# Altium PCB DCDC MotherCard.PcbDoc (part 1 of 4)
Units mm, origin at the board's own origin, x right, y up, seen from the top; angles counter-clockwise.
Board outline 252.5 x 130 mm, 6 copper layers (Top Layer, Layer 2, Layer 3, Layer 4, Layer 5, Bottom Layer), stack 1.582 mm thick; 322 components, 189 nets, 1077 pads, 1461 vias.
Unrouted connection lines stored in the file: 2.
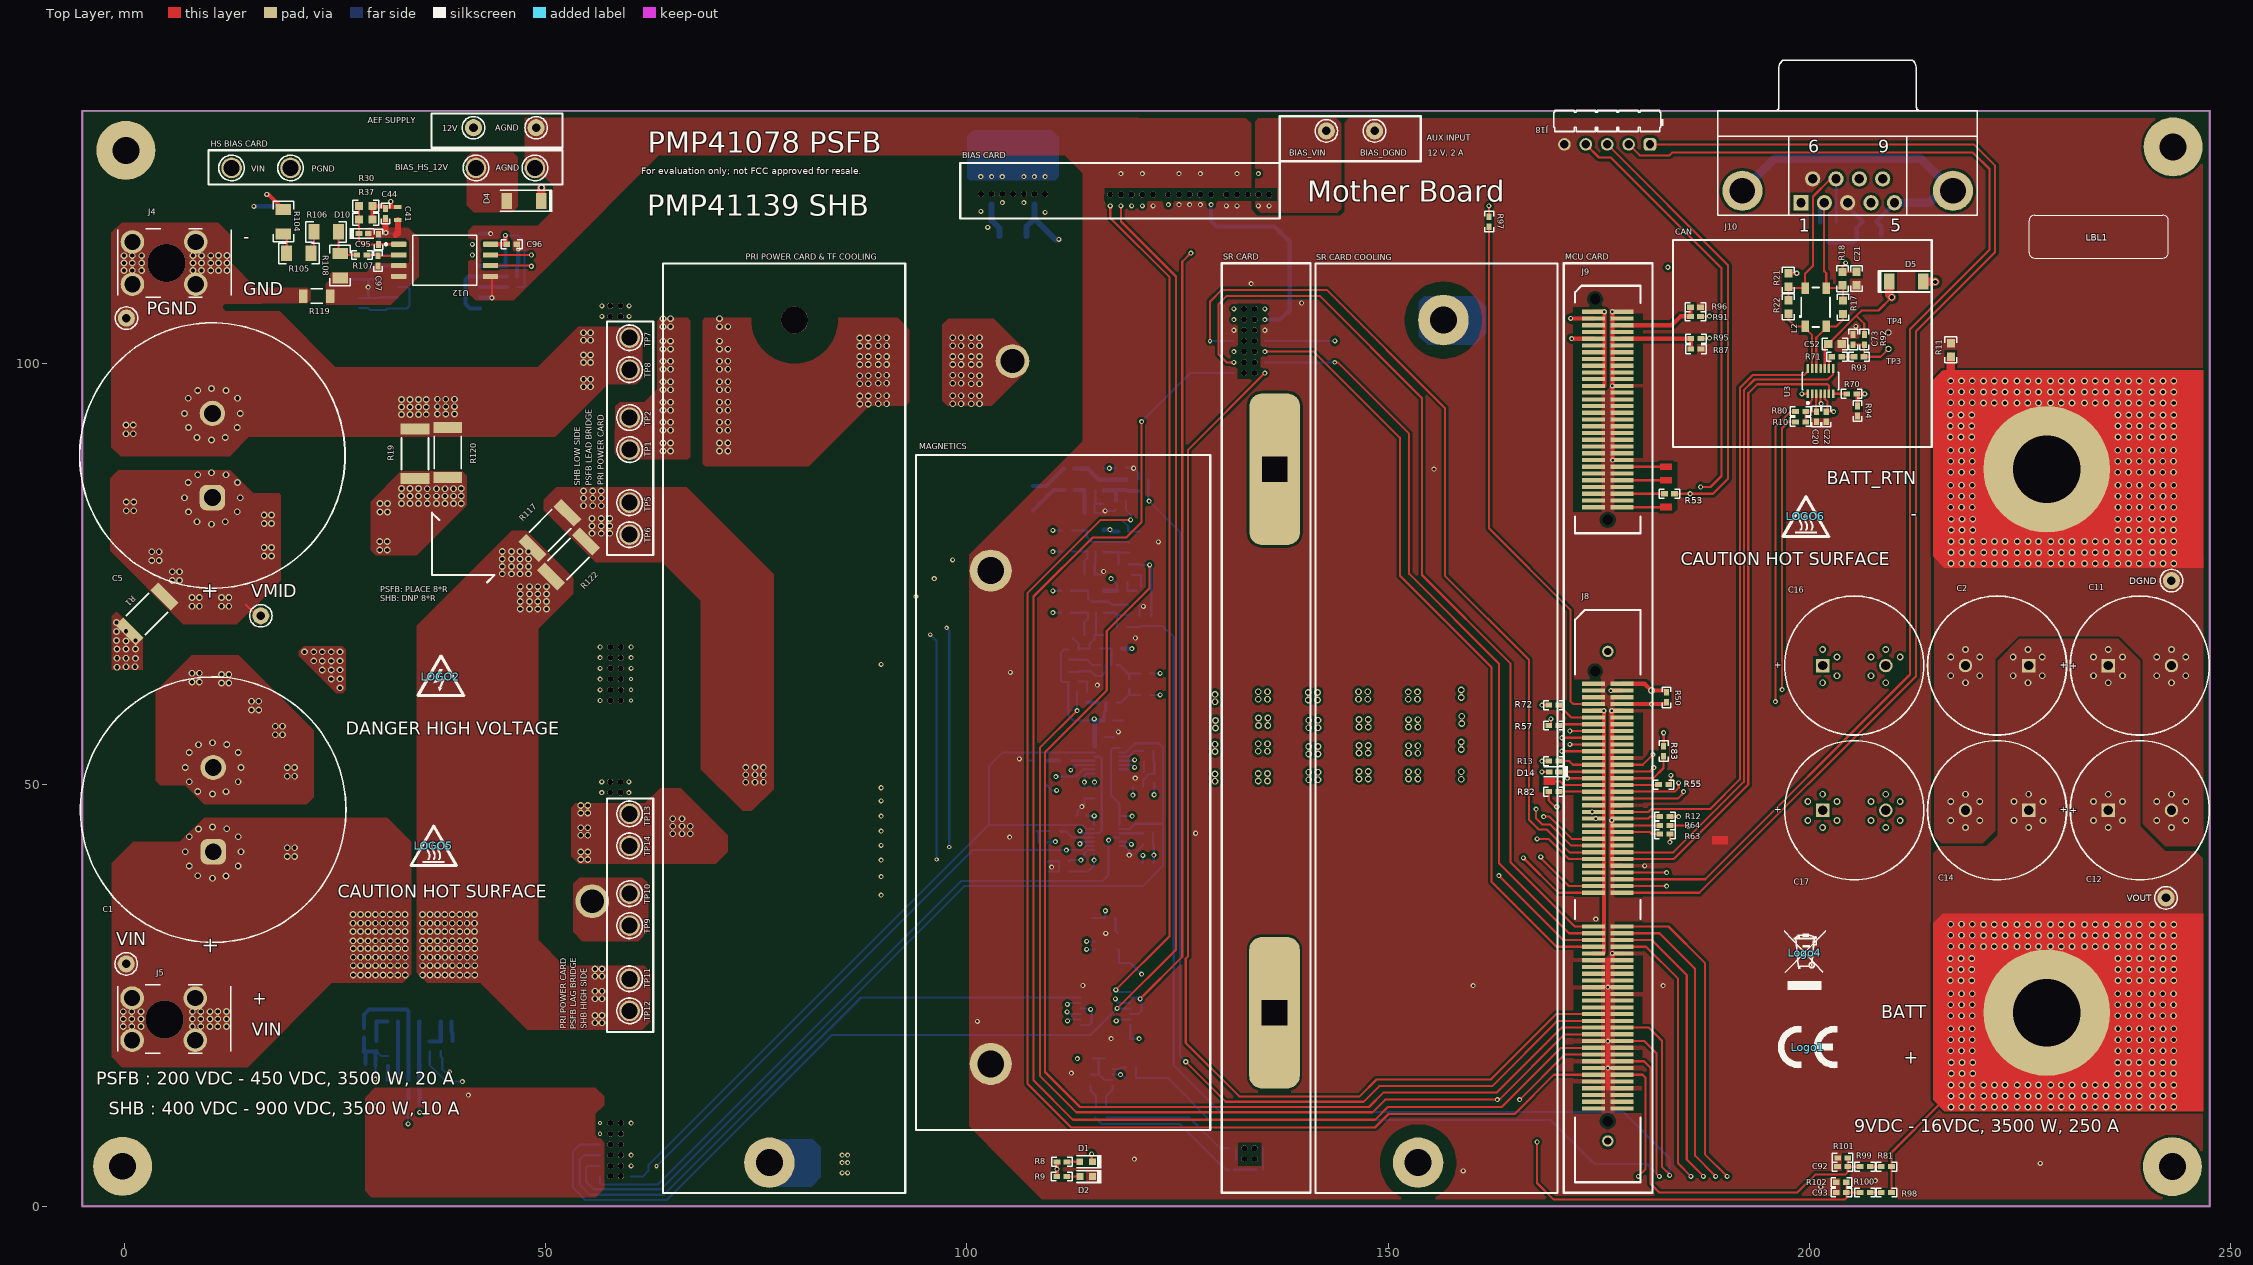
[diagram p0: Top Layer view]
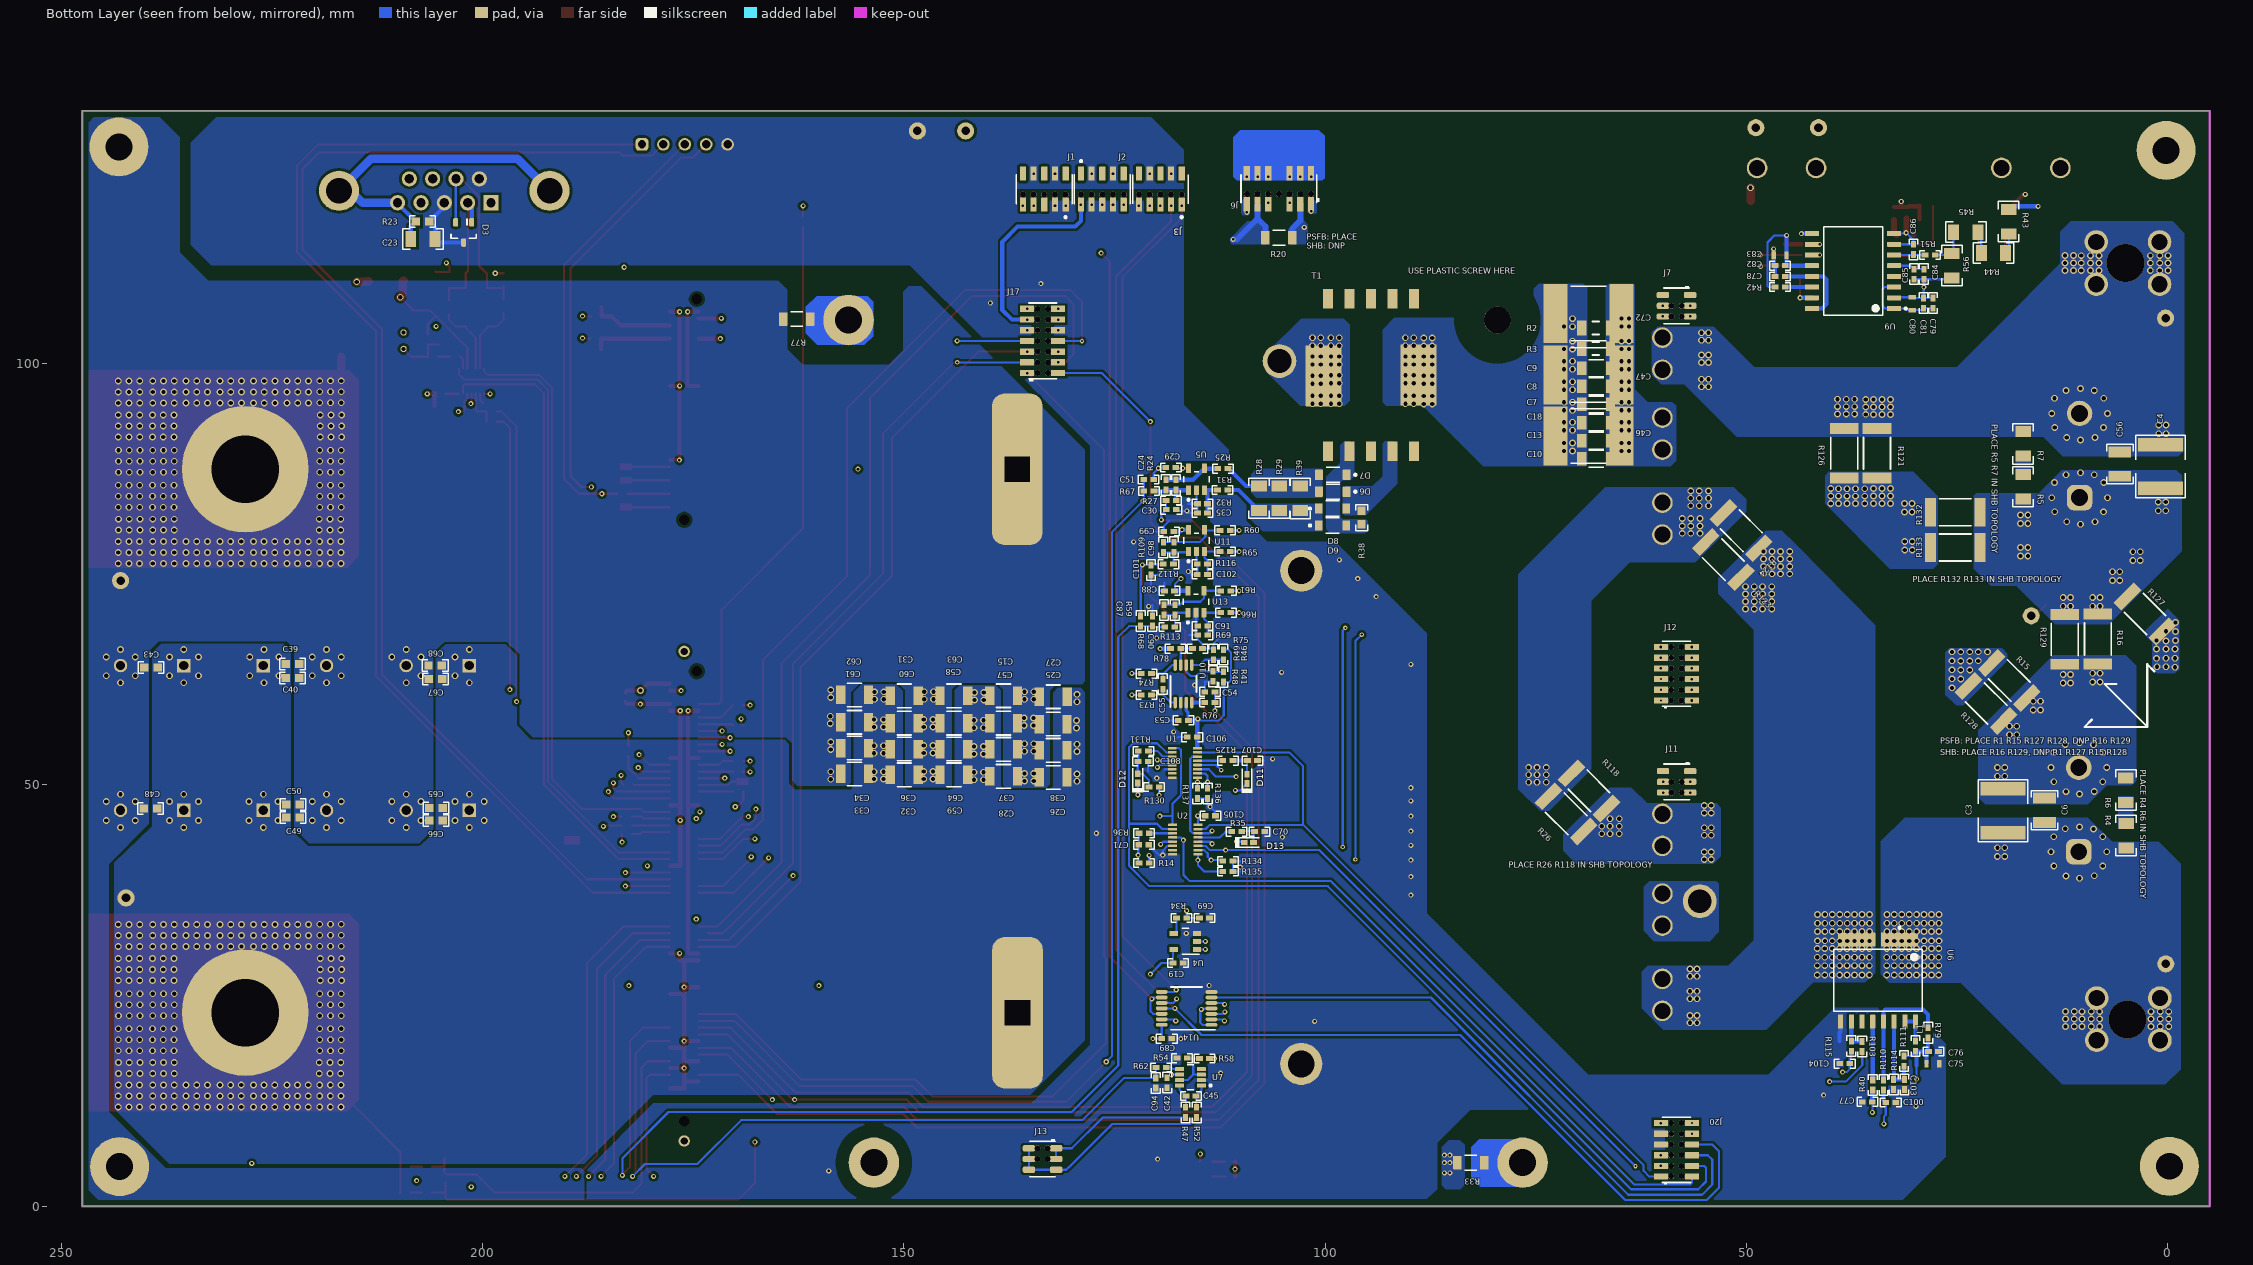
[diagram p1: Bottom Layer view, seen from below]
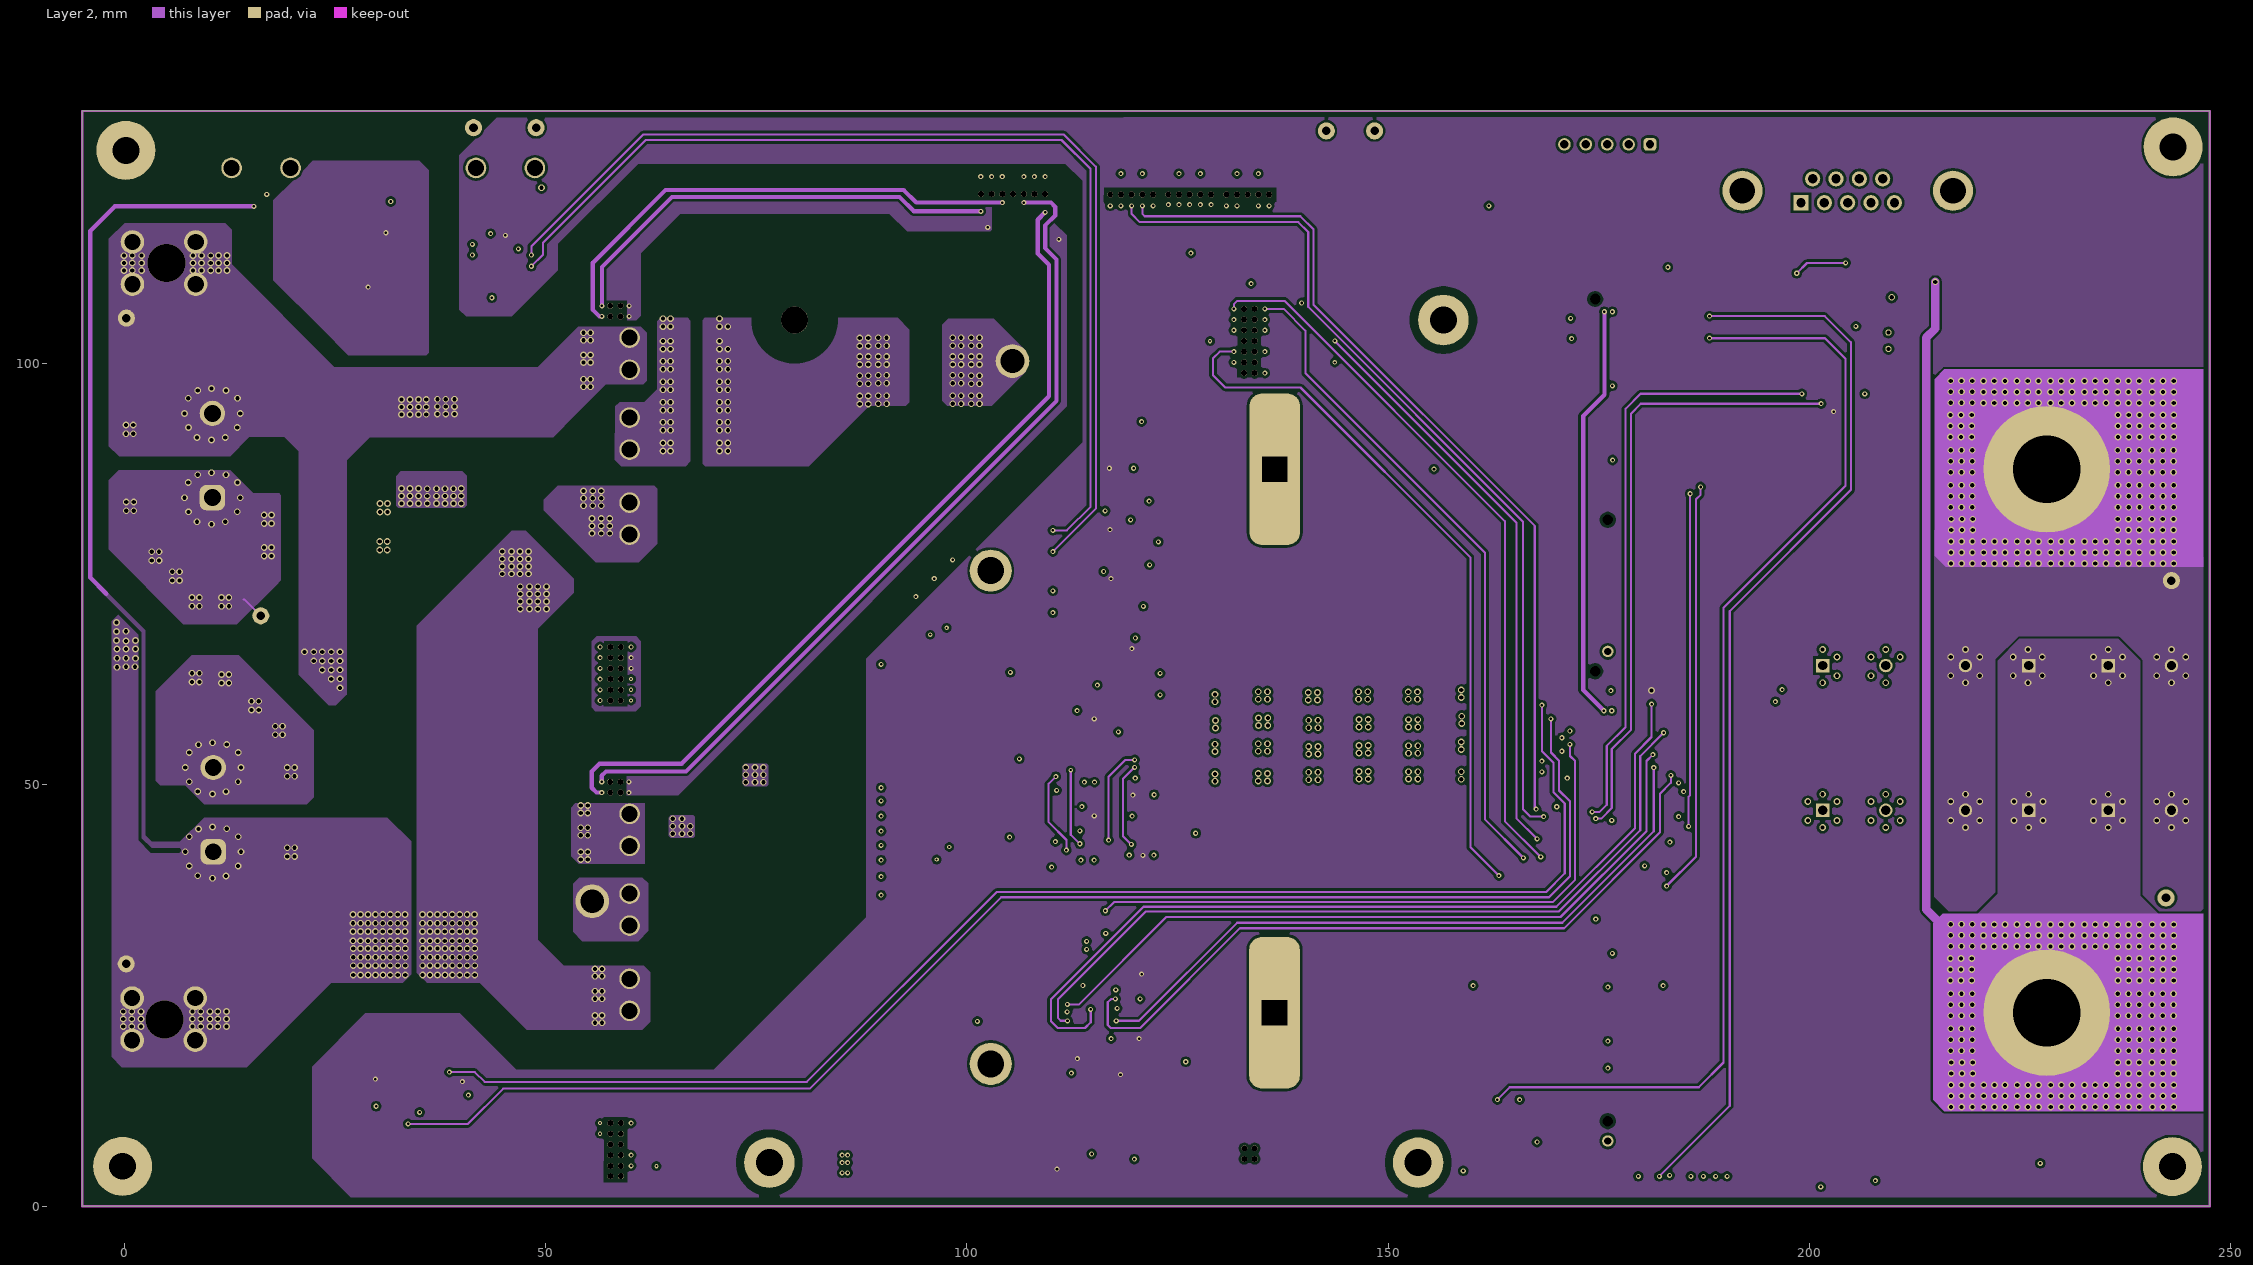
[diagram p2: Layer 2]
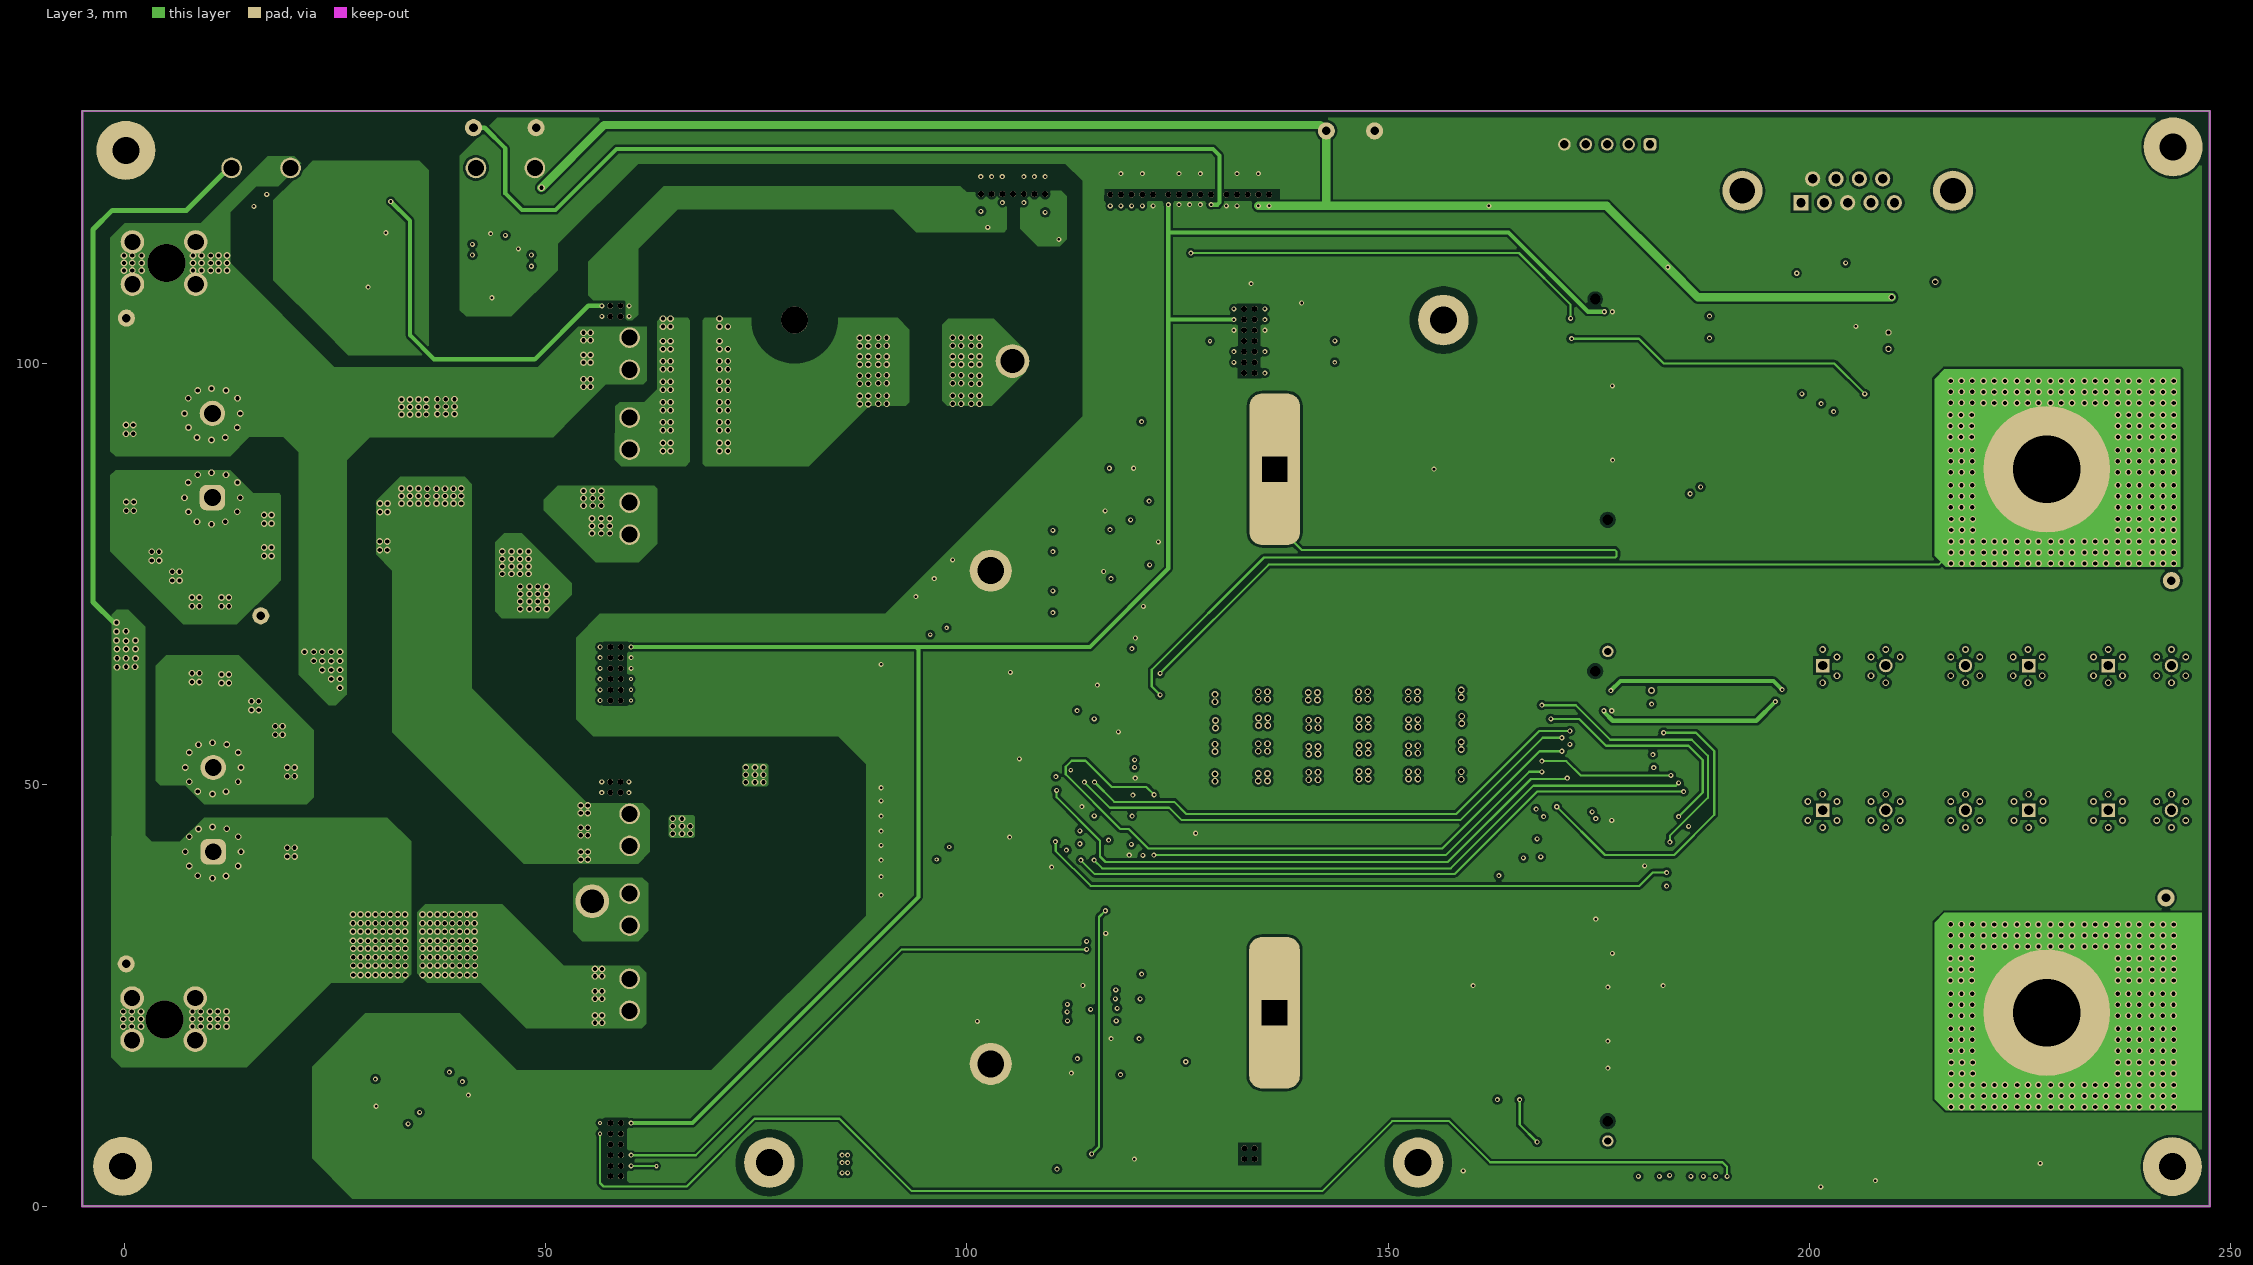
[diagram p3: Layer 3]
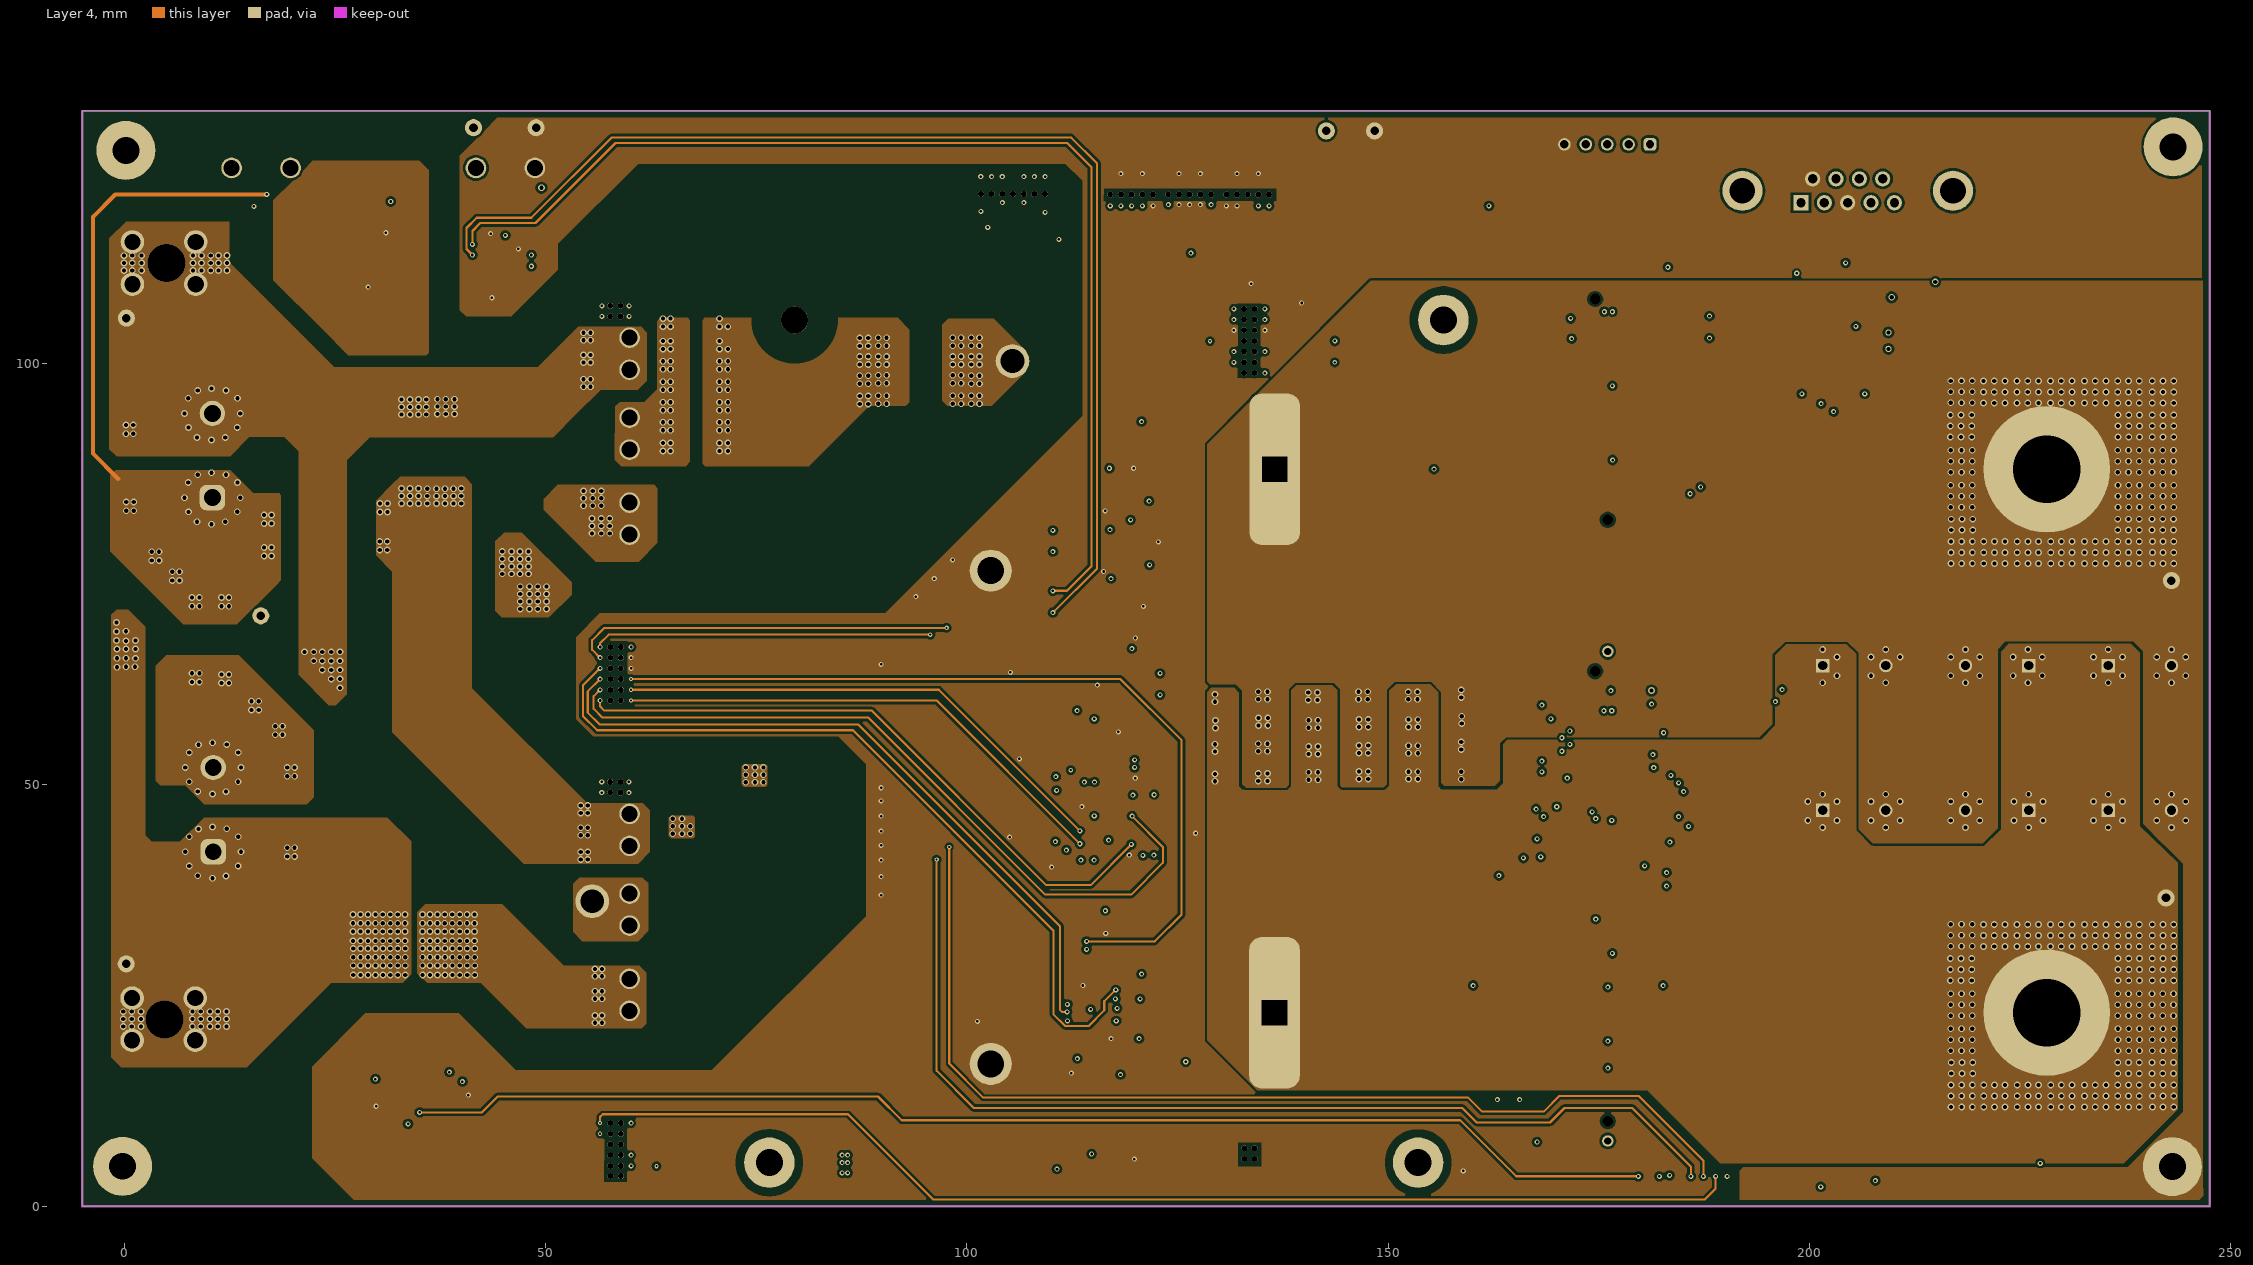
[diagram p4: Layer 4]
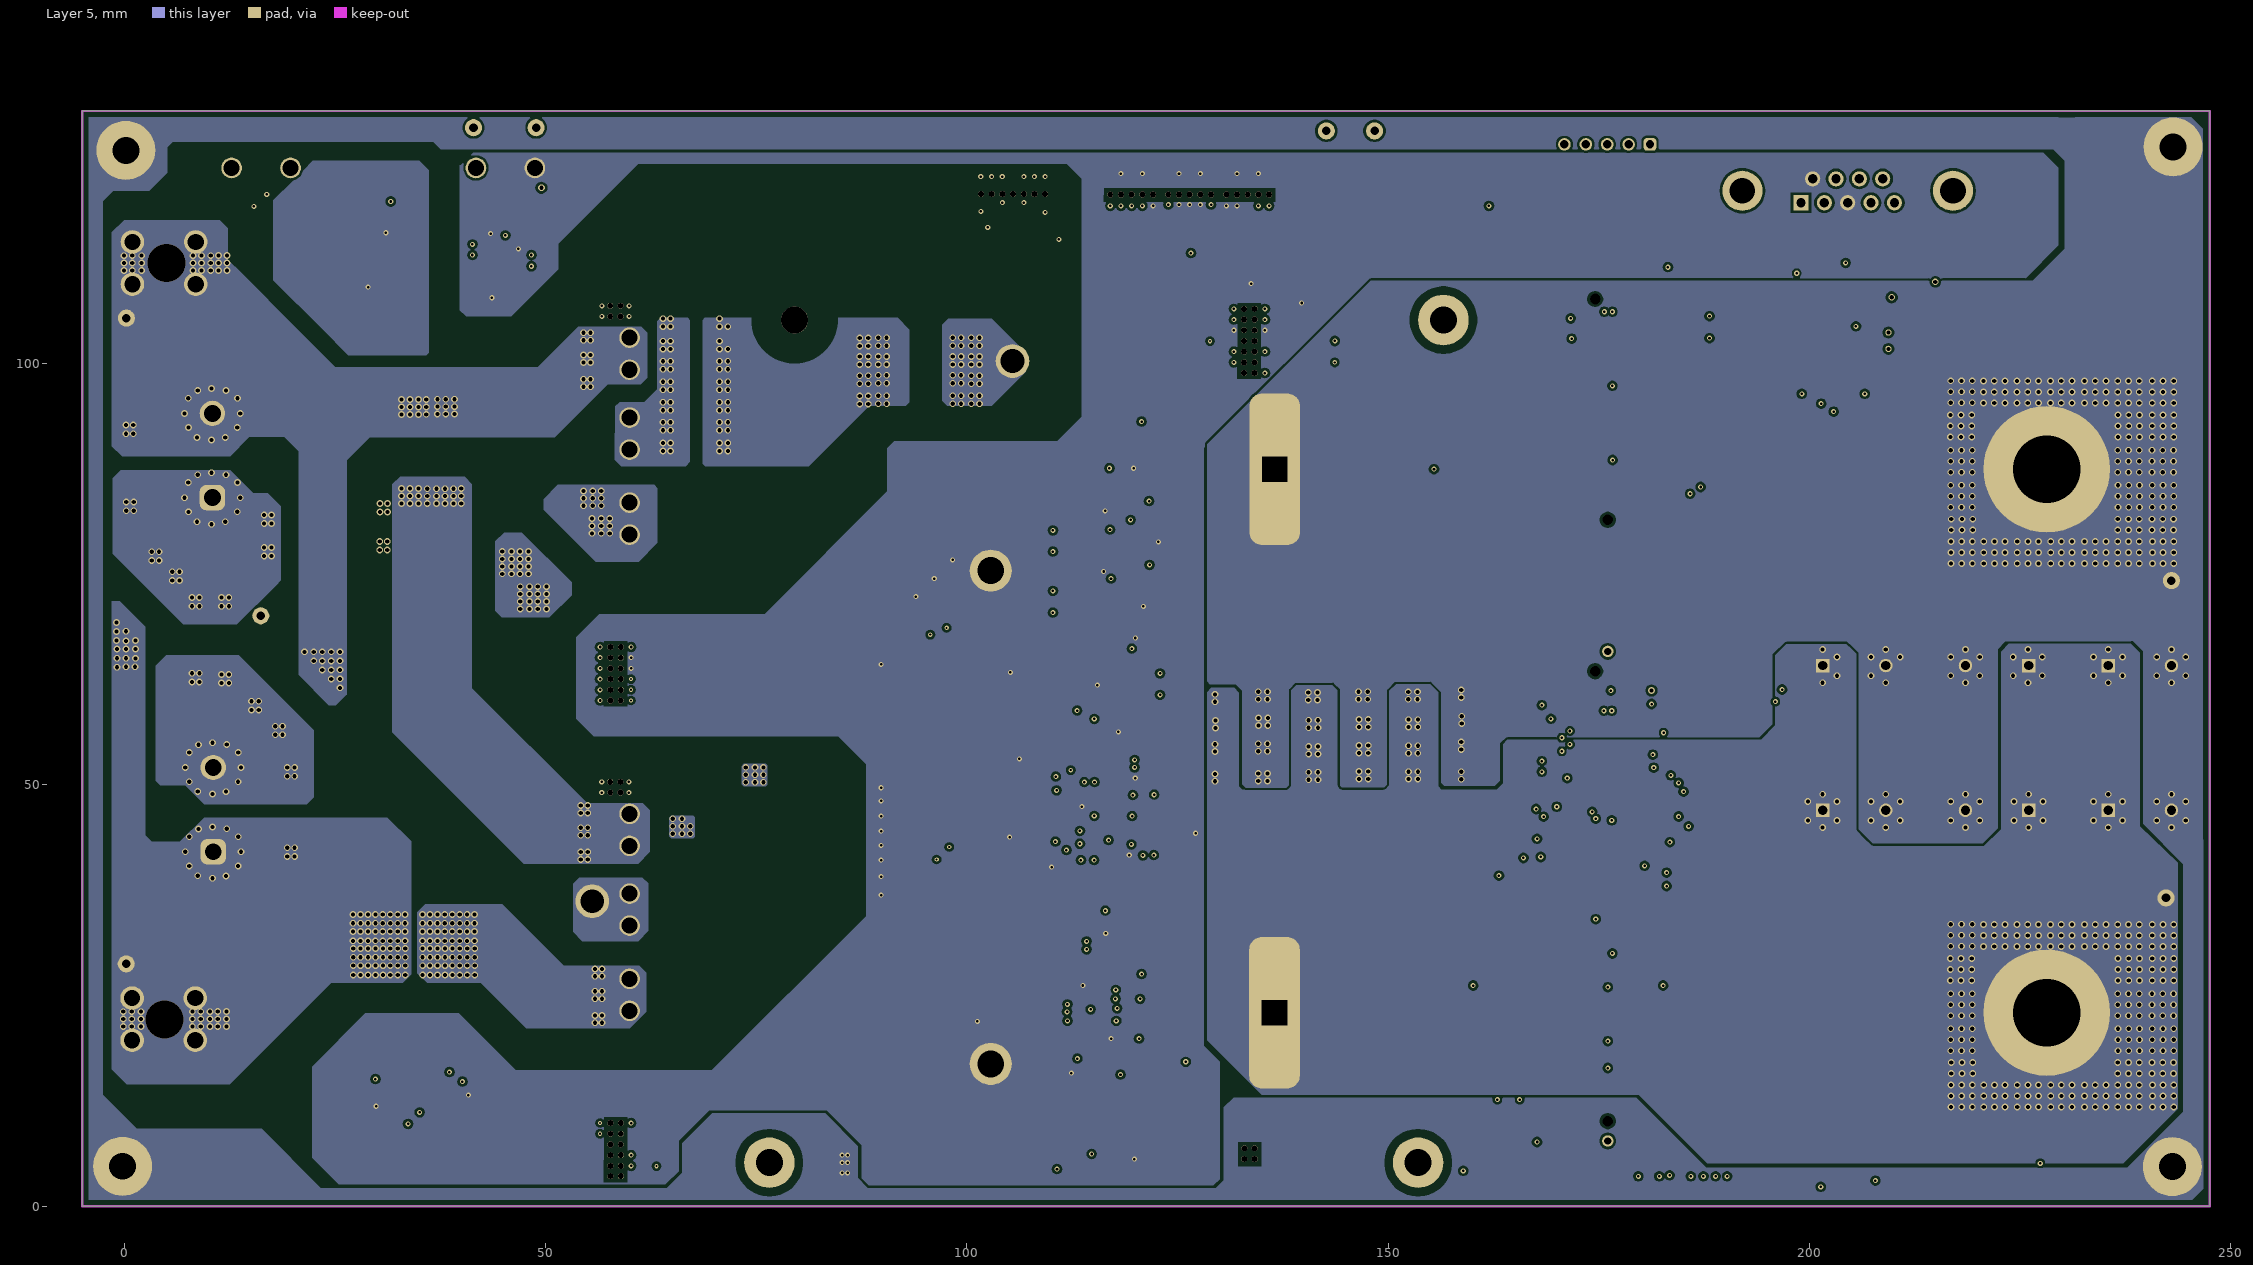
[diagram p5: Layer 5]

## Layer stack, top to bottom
Top Solder: solder mask 0.0102, Solder Resist, Dk 3.5
Top Layer: signal copper 0.07
Dielectric 1: prepreg 0.21, PP-006, Dk 4.1
Layer 2: signal copper 0.07
Dielectric 3: core 0.0711, PP-006, Dk 4.1
Layer 3: signal copper 0.07
Dielectric1: prepreg 0.6, FR-4 High Tg, Dk 4.8
Layer 4: signal copper 0.07
Dielectric 4: core 0.0711, PP-006, Dk 4.1
Layer 5: signal copper 0.07
Dielectric 2: prepreg 0.21, PP-006, Dk 4.1
Bottom Layer: signal copper 0.07
Bottom Solder: solder mask 0.0102, Solder Resist, Dk 3.5

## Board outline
-5,0 -5,130 247.5,130 247.5,0

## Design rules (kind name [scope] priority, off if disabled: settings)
AcuteAngle [All] p1: minimum=4.50000000000000E+0001 checktracksonly=FALSE
AssemblyTestPointUsage [All] p1: valid=2
Clearance Clearance_BoardEdge_MountingHoles [OnCopper and InComponentClass('Mounting Holes') vs IsKeepOut] p1: gap=1.016 ignorepadtopadclearanceinfootprint=FALSE except(0: Arc-Hole Track-Hole SMDPad-Hole THPad-Hole Via-Hole Fill-Hole Poly-Hole Region-Hole Text-Hole)
Clearance Clearance_BoardEdge_Poly [OnCopper and InPoly vs IsKeepOut] p2: gap=0.635 ignorepadtopadclearanceinfootprint=FALSE except(0: Arc-Hole Track-Hole SMDPad-Hole THPad-Hole Via-Hole Fill-Hole Poly-Hole Region-Hole Text-Hole)
Clearance Clearance_BoardEdge [OnCopper and Not InComponentClass('Logo') and not InComponentClass('FiducialMark') and not InRegion(1000,500,4000,800) and Not IsKeepout vs IsKeepOut] p3: gap=0.5 ignorepadtopadclearanceinfootprint=FALSE except(0: Arc-Hole Track-Hole SMDPad-Hole THPad-Hole Via-Hole Fill-Hole Poly-Hole Region-Hole Text-Hole)
Clearance Clearance_Poly [InPolygon] p4: gap=0.3 ignorepadtopadclearanceinfootprint=FALSE except(0: Arc-Hole Track-Hole SMDPad-Hole THPad-Hole Via-Hole Fill-Hole Poly-Hole Region-Hole Text-Hole)
Clearance [All] p5: gap=0.2 ignorepadtopadclearanceinfootprint=FALSE except(0: Arc-Hole Track-Hole SMDPad-THPad SMDPad-Hole THPad-Hole Via-Hole Fill-Hole Poly-Hole Region-Hole Text-Hole)
ComponentClearance ComponentClearance_Logo [All] p1 off: gap=0.254 collisioncheckmode=3 verticalgap=0.254 showdistances=TRUE
ComponentClearance ComponentClearance_ScrewToNut [(HasFootprint('NY PMS 440 0025 PH')) vs (HasFootprint('Keystone_1902C'))] p2 off: gap=0.127 collisioncheckmode=3 verticalgap=0.254 showdistances=FALSE
ComponentClearance ComponentClearance_MountingHoles [InComponentClass('Mounting Holes')] p3 off: gap=0.254 collisioncheckmode=3 verticalgap=2540 showdistances=FALSE
ComponentClearance ComponentClearance_SmallPassives [HasFootprint('0201*') or HasFootprint('0402*') or HasFootprint('0508') or HasFootprint('0603*') or HasFootprint('0612') or HasFootprint('0805*') or HasFootprint('0815*') or HasFootprint('0830*') or HasFootprint('1206*') or HasFootprint('1210*') or HasFootprint('1808*') or HasFootprint('1812*') or HasFootprint('1825*') or HasFootprint('2010*') or HasFootprint('2220*') or HasFootprint('2225*') or HasFootprint('2512*') or HasFootprint('2728*') or HasFootprint('3518*') vs HasFootprint('0201*') or HasFootprint('0402*') or HasFootprint('0508') or HasFootprint('0603*') or HasFootprint('0612') or HasFootprint('0805*') or HasFootprint('0815*') or HasFootprint('0830*') or HasFootprint('1206*') or HasFootprint('1210*') or HasFootprint('1808*') or HasFootprint('1812*') or HasFootprint('1825*') or HasFootprint('2010*') or HasFootprint('2220*') or HasFootprint('2225*') or HasFootprint('2512*') or HasFootprint('2728*') or HasFootprint('3518*')] p4 off: gap=0.254 collisioncheckmode=3 verticalgap=0.254 showdistances=FALSE
ComponentClearance ComponentClearance_THtoSMT [IsThruComponent vs IsSMTComponent] p5 off: gap=0.254 collisioncheckmode=3 verticalgap=2540 showdistances=FALSE
ComponentClearance ComponentClearance_THtoTH [IsThruComponent vs IsThruComponent] p6 off: gap=0.254 collisioncheckmode=3 verticalgap=2540 showdistances=FALSE
ComponentClearance [All] p7 off: gap=0.254 collisioncheckmode=3 verticalgap=0.254 showdistances=FALSE
DiffPairsRouting [All] p1: maxlimit=2.54 minlimit=0.254 mostfreqgap=0.254 toplayer_minwidth=0.381 toplayer_maxwidth=0.381 toplayer_prefwidth=0.381 midlayer1_minwidth=0.381 midlayer1_maxwidth=0.381 midlayer1_prefwidth=0.381 midlayer2_minwidth=0.381 midlayer2_maxwidth=0.381 midlayer2_prefwidth=0.381 midlayer3_minwidth=0.381 midlayer3_maxwidth=0.381 midlayer3_prefwidth=0.381 midlayer4_minwidth=0.381 midlayer4_maxwidth=0.381 midlayer4_prefwidth=0.381 bottomlayer_minwidth=0.381 bottomlayer_maxwidth=0.381 bottomlayer_prefwidth=0.381 maxuncoupledlength=25.4
FabricationTestPointUsage TestPointUsage [All] p1: valid=2 allowmultiple=FALSE
FabricationTestpoint Testpoint [All] p1: side=3 testpointundercomponent=TRUE minsize=1.016 maxsize=2.54 preferedsize=1.524 minholesize=0 maxholesize=1.016 preferedholesize=0.813 testpointgrid=0.025 allowsidetop=TRUE allowsidebottom=TRUE usegrid=TRUE gridtolerance=0
FanoutControl Fanout_LCC [IsLCC] p1: bgadir=Out bgaviamode=Centered fanoutstyle=Auto fanoutdirection=Alternating viagrid=0.025 // Fanout_LCC (Default Rule)
FanoutControl Fanout_BGA [IsBGA] p2: bgadir=Out bgaviamode=Centered fanoutstyle=Auto fanoutdirection=Alternating viagrid=0.025 // Fanout_BGA (Default Rule)
FanoutControl Fanout_Default [All] p4: bgadir=Out bgaviamode=Centered fanoutstyle=Auto fanoutdirection=Alternating viagrid=0.025 // Fanout_Default (Default Rule)
FanoutControl Fanout_Small [(CompPinCount < 5)] p5: bgadir=Out bgaviamode=Centered fanoutstyle=Auto fanoutdirection=OutThenIn viagrid=0.025 // Fanout_Small (Default Rule)
Height [All] p1: minheight=0 maxheight=80 prefheight=12.7
HoleSize [All] p1: absolutevalues=TRUE maxlimit=20 minlimit=0.152 maxpercent=80.000 minpercent=20.000
MinimumAnnularRing [All] p1: minimumring=0
MinimumSolderMaskSliver MinimumSolderMaskSliver_Logo [InComponentClass('Logo') vs InComponentClass('Logo')] p1: minsoldermaskwidth=0.018
MinimumSolderMaskSliver [All] p2: minsoldermaskwidth=0
NetsToIgnore [InNet('No Net')] p1:
PlaneConnect [All] p1: planeconnectstyle=Direct reliefexpansion=0.254 reliefentries=4 reliefconductorwidth=0.254 reliefairgap=0.254
PolygonConnect [All] p1: connectstyle=Direct reliefconductorwidth=0.254 reliefentries=4 polygonreliefangle="90 Angle" airgapwidth=0.254
RoutingCorners [All] p1: cornerstyle=45-Degree minsetback=0.254 maxsetback=2.54
RoutingVias [All] p1: holewidth=0.406 width=0.864 viastyle="Through Hole" minholewidth=0.203 minwidth=0.406 maxholewidth=6 maxwidth=6
SMDToCorner [All] p1: distance=0
SilkToBoardRegionClearance [Not ((IsComment or IsDesignator) And (Hide <> 'False')) and not InRegion(1000,500,4000,800)] p1:
SilkToSilkClearance [All] p1: silktosilkclearance=0
SilkToSolderMaskClearance SilkscreenOverComponentPads [IsPad] p1: minsilkscreentomaskgap=0 clearancetoexposedcopper=TRUE
SolderMaskExpansion [All] p1: expansion=0.076 istentingtop=FALSE
Width [All] p1: maxlimit=2.54 minlimit=0.152 preferedwidth=0.254 checkconnectedcopper=TRUE
13 further rules are at their usual default settings.

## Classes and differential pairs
component class Header: J18
net class VSW: LAG_SW LEAD_SW LEAD_SW_R
net class VHV: 3V3 AGND I_HV_2 I_HV_FILTER LEAD_SW_R NetC24_1 NetC24_2 NetC35_1 NetD6_1 NetD6_2 NetD7_1 NetD8_1 NetT1_1 NetT1_3 NetT1_5 NetT1_6 NetT1_7 NetT1_8 NetT1_9 NetT1_10 VIN VPRI+
net class PGND: AGNDM AGNDP LAG_ISO_12V_L LAG_ISO_-5V_L LEAD_ISO_12V_L LEAD_ISO_-5V_L "NC U4" NetC1_2 NetC79_1 NetC84_1 NetC86_1 NetJ6_5 NetR43_2 NetR44_2 NetR45_2
component class "V Sensor": C41 C44 C78 C79 C80 C81 C82 C83 C84 C85 C86 C87 C88 C90 C91 C92 C93 C95 C96 C97 C98 C99 C101 C102 D10 R30 R37 R42 R43 R44 R45 R51 R56 R59 R60 R61 R65 R66 R68 R69 R81 R98 R99 R100 R101 R102 R104 R105 R106 R107 R108 R109 R112 R113 R116 R119 U9 U11 U12 U13
component class PowerStage: 12V AGND BIAS_DGND BIAS_HS_12V BIAS_VIN C1 C2 C3 C4 C5 C6 C7 C8 C9 C10 C11 C12 C13 C14 C15 C16 C17 C18 C25 C26 C27 C28 C31 C32 C33 C34 C36 C37 C38 C39 C40 C43 C46 C47 C48 C49 C50 C56 C57 C58 C59 C60 C61 C62 C63 C64 C65 C66 C67 C68 C72 D4 D5 DGND J1 J2 J3 J4 J5 J6 J7 J11 J12 J13 J17 J20 PGND R1 R2 R3 R4 R5 R6 R7 R15 R16 R19 R20 R26 R33 R77 R117 R118 R120 R121 R122 R123 R124 R126 R127 R128 R129 R132 R133 TP1 TP2 TP5 TP6 TP7 TP8 TP9 TP10 TP11 TP12 TP13 TP14 VIN VMID VOUT
component class "I Sensor": C24 C29 C30 C35 C42 C45 C51 C53 C54 C55 C75 C76 C77 C94 C100 C103 C104 D6 D7 D8 D9 L1 R24 R25 R27 R28 R29 R31 R32 R38 R39 R40 R41 R46 R47 R48 R49 R52 R54 R58 R62 R67 R73 R74 R75 R76 R78 R79 R103 R110 R111 R114 R115 T1 U5 U6 U7 U10
component class Controller: C19 C20 C21 C22 C23 C52 C69 C70 C71 C73 C89 C105 C106 C107 C108 D1 D2 D3 D11 D12 D13 D14 J8 J9 J10 J18 L2 R8 R9 R10 R11 R12 R13 R14 R17 R18 R21 R22 R23 R34 R35 R36 R50 R53 R55 R57 R63 R64 R70 R71 R72 R80 R82 R83 R87 R91 R92 R93 R94 R95 R96 R97 R125 R130 R131 R134 R135 R136 R137 TP3 TP4 U1 U2 U3 U4 U14
component class "DCDC MotherCard_Hardware": LBL1 Logo1 LOGO2 Logo3 Logo4 LOGO5 LOGO6 ZZ1 ZZ2 ZZ3 ZZ4
component class AssemblyNote: ZZ1 ZZ2 ZZ3 ZZ4
component class Label: LBL1

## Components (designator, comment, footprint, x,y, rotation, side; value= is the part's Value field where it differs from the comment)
12V "5000" Keystone5000 41.438,128 r0 top
AGND "0312-0-15-15-34-27-10-0" Mill-Max_0312-0-15-15-34-27-10-0 48.728,123.225 r90 top
AGND "5001" Keystone5001 48.871,128 r90 top
BIAS_DGND "5001" Keystone5001 148.375,127.625 r90 top
BIAS_HS_12V "0312-0-15-15-34-27-10-0" Mill-Max_0312-0-15-15-34-27-10-0 41.729,123.225 r90 top
BIAS_VIN "5000" Keystone5000 142.65,127.625 r90 top
C1 "LGN2X121MELB45" Nichicon_3000x4500_Snap 10.55,47.075 r90 top value=120uF
C2 "B41896C7188M000" B41896_1600x3150 222.25,64.173 r180 top value=1800uF
C3 "CGA9P1X7T2J474M250KC" 2220_280 19.541,46.95 r90 bottom value=0.47uF
C4 "CGA9P1X7T2J474M250KC" 2220_280 0.857,87.791 r90 bottom value=0.47uF
C5 "LGN2X121MELB45" Nichicon_3000x4500_Snap 10.45,89.1 r90 top value=120uF
C6 "CGA6J4C0G2J103J125AA" 1210_150 14.625,47.009 r90 bottom value=0.01uF
C7 "CGA5L3X7R1H225K160AB" 1206_180 67.825,95.157 r180 bottom value=2.2uF
C8 "CGA5L3X7R1H225K160AB" 1206_180 67.825,97.303 r180 bottom value=2.2uF
C9 "CGA5L3X7R1H225K160AB" 1206_180 67.825,99.45 r180 bottom value=2.2uF
C10 "CGA5L3X7R1H225K160AB" 1206_180 67.825,88.717 r180 bottom value=2.2uF
C11 "B41896C7188M000" B41896_1600x3150 239.2,64.173 r0 top value=1800uF
C12 "B41896C7188M000" B41896_1600x3150 239.2,47 r0 top value=1800uF
C13 "CGA5L3X7R1H225K160AB" 1206_180 67.825,90.863 r180 bottom value=2.2uF
C14 "B41896C7188M000" B41896_1600x3150 222.25,47 r180 top value=1800uF
C15 "CGA6P3X7S1H106K250AE" 1210_280 138.15,60.594 r180 bottom value=10uF
C16 "B41896C7188M000" B41896_1600x3150 205.3,64.173 r0 top value=1800uF
C17 "B41896C7188M000" B41896_1600x3150 205.3,47 r0 top value=1800uF
C18 "CGA5L3X7R1H225K160AB" 1206_180 67.825,93.01 r180 bottom value=2.2uF
C19 "CGA2B3X7R1E104K050BB" 0402 117.441,28.865 r180 bottom value=0.1uF
C20 "CGA2B3X7R1E104K050BB" 0402 200.801,93.703 r270 top value=0.1uF
C21 "CGA3E2X7R2A472K080AA" 0603 205.55,110.125 r270 top value=4700pF
C22 "CGA2B3X7R1E104K050BB" 0402 201.981,93.703 r270 top value=0.1uF
C23 "C1206C103J2GACAUTO" 1206 207.059,114.8 r180 bottom value=0.01uF
C24 "04025U100CAT2A" 0402 118.903,85.617 r90 bottom value=10pF
C25 "CGA6P3X7S1H106K250AE" 1210_280 132.262,57.231 r0 bottom value=10uF
C26 "CGA6P3X7S1H106K250AE" 1210_280 132.262,50.896 r0 bottom value=10uF
C27 "CGA6P3X7S1H106K250AE" 1210_280 132.255,60.471 r0 bottom value=10uF
C28 "CGA6P3X7S1H106K250AE" 1210_280 138.155,51.019 r180 bottom value=10uF
C29 "CGA2B3X7R1E104K050BB" 0402 118.308,87.685 r0 bottom value=0.1uF
C30 "AC0402KRX7R7BB221" 0402 118.254,82.668 r180 bottom value=220pF
C31 "CGA6P3X7S1H106K250AE" 1210_280 149.939,60.58 r180 bottom value=10uF
C32 "CGA6P3X7S1H106K250AE" 1210_280 149.941,51.205 r180 bottom value=10uF
C33 "CGA6P3X7S1H106K250AE" 1210_280 155.834,51.306 r0 bottom value=10uF
C34 "CGA6P3X7S1H106K250AE" 1210_280 155.834,54.381 r0 bottom value=10uF
C35 "04025U100CAT2A" 0402 114.54,82.278 r0 bottom value=10pF
C36 "CGA6P3X7S1H106K250AE" 1210_280 149.941,54.266 r180 bottom value=10uF
C37 "CGA6P3X7S1H106K250AE" 1210_280 138.155,54.229 r180 bottom value=10uF
C38 "CGA6P3X7S1H106K250AE" 1210_280 132.262,54.106 r0 bottom value=10uF
C39 "06035C104KAZ2A" 0603 222.525,64.371 r180 bottom value=0.1uF
C40 "06035C104KAZ2A" 0603 222.525,62.712 r180 bottom value=0.1uF
C41 "CGA3E1X7R1E105K080AC" 0603S 32.462,117.822 r270 top value=1uF
C42 "CGA2B3X7R1E104K050BB" 0402 118.743,14.667 r270 bottom value=0.1uF
C43 "06035C104KAZ2A" 0603 239.35,63.95 r0 bottom value=0.1uF
C44 "CGA2B3X7R1E104K050BB" 0402 30.993,117.822 r270 top value=0.1uF
C45 "AC0402KRX7R7BB221" 0402 115.917,13.091 r180 bottom value=220pF
C46 "B58035U7105M052" FP-B58035U7105M052_SMD2-MFG 68.725,91.412 r0 bottom value=1µF
C47 "B58035U7105M052" FP-B58035U7105M052_SMD2-MFG 68.725,98.658 r0 bottom value=1µF
C48 "06035C104KAZ2A" 0603 239.375,47.2 r0 bottom value=0.1uF
C49 "06035C104KAZ2A" 0603 222.475,46.125 r180 bottom value=0.1uF
C50 "06035C104KAZ2A" 0603 222.475,47.675 r180 bottom value=0.1uF
C51 "GCM155R71H222KA37D" 0402 120.931,86.252 r180 bottom value=2200pF
C52 "06035C104KAZ2A" 0603 203,102.333 r0 top value=0.1uF
C53 "CGA2B3X7R1E104K050BB" 0402 116.809,57.672 r0 bottom value=0.1uF
C54 "AC0402KRX7R7BB221" 0402 113.666,61.055 r0 bottom value=220pF
C55 "AC0402KRX7R7BB221" 0402 119.258,61.958 r90 bottom value=220pF
C56 "CGA6J4C0G2J103J125AA" 1210_150 5.681,88.091 r90 bottom value=0.01uF
C57 "CGA6P3X7S1H106K250AE" 1210_280 138.155,57.341 r180 bottom value=10uF
C58 "CGA6P3X7S1H106K250AE" 1210_280 144.048,57.339 r0 bottom value=10uF
C59 "CGA6P3X7S1H106K250AE" 1210_280 144.048,54.266 r0 bottom value=10uF
C60 "CGA6P3X7S1H106K250AE" 1210_280 149.941,57.339 r180 bottom value=10uF
C61 "CGA6P3X7S1H106K250AE" 1210_280 155.834,57.441 r0 bottom value=10uF
C62 "CGA6P3X7S1H106K250AE" 1210_280 155.834,60.681 r0 bottom value=10uF
C63 "CGA6P3X7S1H106K250AE" 1210_280 144.045,60.58 r0 bottom value=10uF
C64 "CGA6P3X7S1H106K250AE" 1210_280 144.048,51.205 r0 bottom value=10uF
C65 "06035C104KAZ2A" 0603 205.525,47.267 r0 bottom value=0.1uF
C66 "06035C104KAZ2A" 0603 205.525,45.782 r0 bottom value=0.1uF
C67 "06035C104KAZ2A" 0603 205.561,62.575 r0 bottom value=0.1uF
C68 "06035C104KAZ2A" 0603 205.605,64.173 r0 bottom value=0.1uF
C69 "GCM155R71H222KA37D" 0402 114.312,34.224 r180 bottom value=2200pF
C70 "GCM155R71H222KA37D" 0402 107.768,44.458 r180 bottom value=2200pF
C71 "GCM155R71H222KA37D" 0402 121.509,42.908 r180 bottom value=2200pF
C72 "B58035U7105M052" FP-B58035U7105M052_SMD2-MFG 68.725,105.941 r0 bottom value=1µF
C73 "CGA2B3X7R1H103K050BB" 0402 205.179,102.853 r90 top value=0.01uF
C75 "CGA3E1X7R1E105K080AC" 0603S 27.869,16.925 r180 bottom value=1uF
C76 "CGA2B3X7R1E104K050BB" 0402 27.795,18.365 r180 bottom value=0.1uF
C77 "AC0402KRX7R7BB221" 0402 35.65,12.39 r0 bottom value=220pF
C78 "CGA2B3X7R1E104K050BB" 0402 45.993,110.356 r0 bottom value=0.1uF
C79 "CGA2B3X7R1E104K050BB" 0402 27.843,107.191 r90 bottom value=0.1uF
C80 "CGA3E1X7R1E105K080AC" 0603S 30.293,107.116 r90 bottom value=1uF
C81 "GCM155R71H222KA37D" 0402 28.968,107.191 r90 bottom value=2200pF
C82 "GCM155R71H222KA37D" 0402 46,111.626 r0 bottom value=2200pF
C83 "CGA3E1X7R1E105K080AC" 0603S 46,112.896 r0 bottom value=1uF
C84 "CGA2B3X7R1E104K050BB" 0402 28.943,110.616 r270 bottom value=0.1uF
C85 "GCM155R71H222KA37D" 0402 30.118,110.616 r270 bottom value=2200pF
C86 "CGA2B3X7R1H103K050BB" 0402 30.168,113.566 r90 bottom value=0.01uF
C87 "AC0402KRX7R7BB221" 0402 119.108,70.786 r270 bottom value=220pF
C88 "CGA2B3X7R1E104K050BB" 0402 118.464,73.043 r0 bottom value=0.1uF
C89 "CGA2B3X7R1E104K050BB" 0402 118.789,19.889 r180 bottom value=0.1uF
C90 "AC0402KRX7R7BB221" 0402 120.499,69.455 r90 bottom value=220pF
C91 "AC0402KRX7R7BB221" 0402 114.521,68.855 r0 bottom value=220pF
C92 "AC0402KRX7R7BB221" 0402 203.926,4.7 r180 top value=220pF
C93 "AC0402KRX7R7BB221" 0402 203.765,1.629 r180 top value=220pF
C94 "AC0402KRX7R7BB221" 0402 120.091,14.638 r270 bottom value=220pF
C95 "CGA2B3X7R1E104K050BB" 0402 30.168,114.751 r90 top value=0.1uF
C96 "CGA2B3X7R1E104K050BB" 0402 45.981,114.171 r0 top value=0.1uF
C97 "CGA2B3X7R1H103K050BB" 0402 30.118,112.195 r270 top value=0.01uF
C98 "AC0402KRX7R7BB221" 0402 117.938,78.217 r270 bottom value=220pF
C99 "CGA2B3X7R1E104K050BB" 0402 118.544,80.094 r0 bottom value=0.1uF
C100 "GCM155R71H222KA37D" 0402 32.863,12.323 r180 bottom value=2200pF
C101 "AC0402KRX7R7BB221" 0402 120.662,75.513 r270 bottom value=220pF
C102 "AC0402KRX7R7BB221" 0402 114.56,74.993 r0 bottom value=220pF
C103 "AC0402KRX7R7BB221" 0402 31.229,14.46 r270 bottom value=220pF
C104 "GCM155R71H222KA37D" 0402 38.325,16.925 r0 bottom value=2200pF
C105 "CGA2B3X7R1E104K050BB" 0402 113.613,46.346 r180 bottom value=0.1uF
C106 "CGA2B3X7R1E104K050BB" 0402 115.763,55.678 r0 bottom value=0.1uF
C107 "GCM155R71H222KA37D" 0402 108.611,52.89 r180 bottom value=2200pF
C108 "GCM155R71H222KA37D" 0402 121.591,52.806 r180 bottom value=2200pF
D1 "LTST-C190CKT" LED_LTST-C190_Red 114.142,5.285 r0 top value=Red
D2 "LTST-C190GKT" LED_LTST-C190 114.162,3.523 r0 top value=Green
D3 "NUP2105LT1G" SOT-23 202.225,115.575 r270 bottom value=24V
D4 "FSV340AF" SMAF 47.425,119.325 r180 top value=40V
D5 "FSV340AF" SMAF 211.476,109.757 r0 top value=40V
D6 "MBR130T3G" FP-MBR130T3G_SOD123-MFG 99.082,84.807 r0 bottom
D7 "MBR130T3G" FP-MBR130T3G_SOD123-MFG 99.082,86.813 r0 bottom
D8 "MBR130T3G" FP-MBR130T3G_SOD123-MFG 99.118,82.802 r180 bottom
D9 "MBR130T3G" FP-MBR130T3G_SOD123-MFG 99.118,80.796 r180 bottom
D10 "EDZVFHT2R4.7B" SOD-523 28.397,115.436 r0 top value=4.7V
D11 "RB521S30T1G" SOD-523 109.259,50.717 r90 bottom value=30V
D12 "RB521S30T1G" SOD-523 122.226,50.774 r90 bottom value=30V
D13 "RB521S30T1G" SOD-523 109.029,43.166 r180 bottom value=30V
D14 "RB521S30T1G" SOD-523 169.656,51.566 r180 top value=30V
DGND "5001" Keystone5001 242.95,74.25 r90 top
J1 "FLE-105-01-G-DV" FP-FLE-105-01-G-DV_HDR10-MFG 133.32,120.713 r0 bottom
J2 "FLE-105-01-G-DV" FP-FLE-105-01-G-DV_HDR10-MFG 126.435,120.713 r180 bottom
J3 "FLE-105-01-G-DV" FP-FLE-105-01-G-DV_HDR10-MFG 119.544,120.713 r0 bottom
J4 "8199" SCREW_TERMINAL_8199 5.966,111.941 r0 top
J5 "8199" SCREW_TERMINAL_8199 5.925,22.2 r0 top
J6 "FLE-107-01-G-DV" Samtec_FLE-107-01-x-DV#1 105.475,120.762 r0 bottom
J7 "CLP-103-02-G-D" Samtec_CLP-103-02-x-D 58.29,106.87 r180 bottom
J8 "HSEC8-160-01-L-DV-A-BL" controlCARD-120HSEC 176.076,34.963 r90 top
J9 "HSEC8-130-01-L-DV-A" controlCARD-180HSEC-60pinAddon 176.054,94.563 r90 top
J10 "182-009-213R171" NORCOMP_182-009-213R171 204.524,130.015 r0 top
J11 "CLP-103-02-G-D" Samtec_CLP-103-02-x-D 58.275,50.375 r180 bottom
J12 "FLE-106-01-G-DV-A" Samtec_FLE-106-01-x-DV-A 58.3,63.2 r90 bottom
J13 "CLP-103-02-G-D" Samtec_CLP-103-02-x-D 133.53,5.61 r180 bottom
J17 "FLE-107-01-G-DV" Samtec_FLE-107-01-x-DV#2 133.518,102.695 r90 bottom
J18 "PRPC005SBAN-M71RC" Sullins_PRxC005SBAN-M71RC 175.987,126.025 r180 top
J20 "FLE-106-01-G-DV-A" Samtec_FLE-106-01-x-DV-A 58.3,6.7 r90 bottom
L1 "BLM15AX601SN1D" 0402 29.923,19 r90 bottom value="600 ohm"
L2 "ACT45B-101-2P-TL003" ACT45B 200.729,106.696 r90 top value=100uH
LBL1 "THT-14-423-10" Label_650x200 234.325,115.075 r0 top
Logo1 "CE Mark" CE_Mark_5mm 199.757,18.9 r0 top
LOGO2 "DANGER HIGH VOLTAGE" IEC_HighVoltage_Small 37.575,62.85 r0 top
Logo3 "FCC disclaimer" FCC_disclaimer 144,-18.75 r0 top
Logo4 "WEEE logo" WEEE_Minimum 199.4,30.1 r0 top
LOGO5 "CAUTION HOT SURFACE" IEC_HotSurface_Small 36.711,42.78 r0 top
LOGO6 "CAUTION HOT SURFACE" IEC_HotSurface_Small 199.573,81.863 r0 top
PGND "5001" Keystone5001 0.25,105.4 r90 top
PGND "0312-0-15-15-34-27-10-0" Mill-Max_0312-0-15-15-34-27-10-0 19.729,123.225 r90 top
R1 "RMC1JPTE" 2512 2.686,70.291 r45 top value=0
R2 "CRCW120610K0JNEA" 1206L#1 67.85,104.227 r0 bottom value=10k
R3 "CRCW120610K0JNEA" 1206L#2 67.85,101.802 r0 bottom value=10k
R4 "CRCW1206100KJNEA" 1206 4.925,43.993 r270 bottom value=100k
R5 "CRCW1206100KJNEA" 1206 17.149,85.391 r270 bottom value=100k
R6 "CRCW1206100KJNEA" 1206 4.952,49.394 r270 bottom value=100k
R7 "CRCW1206100KJNEA" 1206 17.149,90.491 r270 bottom value=100k
R8 "ERA-2AEB752X" 0402 111.286,5.279 r180 top value=7.50k
R9 "ERA-2AEB752X" 0402 111.249,3.523 r180 top value=7.50k
R10 "CRCW04020000Z0ED" 0402 198.938,93.103 r180 top value=0
R11 "RMCF0603ZT0R00" 0603 216.764,101.642 r90 top value=0
R12 "CRCW04020000Z0ED" 0402 182.824,46.24 r180 top value=0
R13 "CRCW04020000Z0ED" 0402 169.656,52.828 r180 top value=0
R14 "RK73H1ETTP1002F" 0402 121.469,40.735 r180 bottom value=10.0k
R15 "RMC1JPTE" 2512 18.8,62.4 r225 bottom value=0
R16 "RMC1JPTE" 2512 8.28,67.325 r90 bottom value=0
R17 "RMCF0603ZT0R00" 0603 203.954,106.696 r90 top value=0
R18 "CRCW060360K4FKEA" 0603 203.925,110.083 r270 top value=60.4k
R19 "RMC1JPTE" 2512 34.501,89.32 r90 top value=0
R20 "RMCF1206ZT0R00" FP-RMCF1206ZT0R00_1206-MFG 105.475,114.95 r180 bottom value=0
R21 "CRCW060360K4FKEA" 0603 197.479,109.921 r90 top value=60.4k
R22 "RMCF0603ZT0R00" 0603 197.479,106.746 r90 top value=0
R23 "CRCW06031M00FKEA" 0603 207.109,116.87 r0 bottom value=1.00Meg
R24 "ERJ-2RKF2001X" 0402 117.678,85.617 r270 bottom value=2.00k
R25 "CRCW04021K00FKED" 0402 112.124,87.537 r0 bottom value=1.00k
R26 "RMC1JPTE" 2512 71.385,46.568 r45 bottom value=0
R27 "RMCF0402JT10R0" 0402 118.274,83.772 r0 bottom value=10.0
R28 "CRCW120615R0FKEA" 1206 107.84,84.029 r90 bottom value=15.0
R29 "CRCW120615R0FKEA" 1206 105.415,84.029 r90 bottom value=15.0
R30 "CRCW06032K00FKEA" 0603 28.652,118.732 r180 top value=2.00k
R31 "CRCW04021K00FKED" 0402 112.154,85.002 r0 bottom value=1.00k
R32 "ERJ-2RKF2001X" 0402 114.543,83.378 r180 bottom value=2.00k
R33 "RMCF1206ZT0R00" FP-RMCF1206ZT0R00_1206-MFG 82.694,5.175 r0 bottom value=0
R34 "CRCW0402100RFKED" 0402 117.027,34.224 r180 bottom value=100
R35 "CRCW0402100RFKED" 0402 110.486,44.458 r180 bottom value=100
R36 "CRCW0402100RFKED" 0402 121.469,44.269 r0 bottom value=100
R37 "CRCW06032K00FKEA" 0603 28.652,117.132 r180 top value=2.00k
R38 "CRCW06032K00FKEA" 0603 95.647,81.72 r90 bottom value=2.00k
R39 "CRCW120615R0FKEA" 1206 102.95,84.011 r90 bottom value=15.0
R40 "RMCF0402JT10R0" 0402 35.003,14.393 r270 bottom value=10.0
R41 "CRCW04020000Z0ED" 0402 112.074,62.822 r90 bottom value=0
R42 "CRCW040247K5FKED" 0402 45.993,109.086 r180 bottom value=47.5k
R43 "ERJ-8ENF8453V" 1206 18.879,116.846 r270 bottom value=845k
R44 "ERJ-8ENF8453V" 1206 20.67,113.131 r0 bottom value=845k
R45 "ERJ-8ENF8453V" 1206 23.951,115.616 r0 bottom value=845k
R46 "CRCW04020000Z0ED" 0402 112.052,65.46 r270 bottom value=0
R47 "RMCF0402JT10R0" 0402 116.555,11.139 r90 bottom value=10.0
R48 "CRCW04020000Z0ED" 0402 113.301,62.902 r270 bottom value=0
R49 "CRCW04020000Z0ED" 0402 113.258,65.46 r270 bottom value=0
R50 "RK73H1ETTP1002F" 0402 183.015,60.406 r90 top value=10.0k
R51 "CRCW04020000Z0ED" 0402 28.186,112.896 r180 bottom value=0
R52 "RMCF0402JT10R0" 0402 115.231,11.139 r90 bottom value=10.0
R53 "CRCW04020000Z0ED" 0402 183.382,84.563 r180 top value=0
R54 "ERA-2AEB752X" 0402 116.966,17.582 r180 bottom value=7.50k
R55 "CRCW04020000Z0ED" 0402 182.675,50.032 r180 top value=0
R56 "CRCW12069K09FKEA" 1206 25.618,111.631 r90 bottom value=9.09k
R57 "CRCW04020000Z0ED" 0402 169.656,57.058 r180 top value=0
R58 "CRCW040215K0FKED" 0402 114.315,17.53 r180 bottom value=15.0k
R59 "CRCW040215K0FKED" 0402 117.829,70.786 r270 bottom value=15.0k
R60 "RK73H1ETTP1002F" 0402 111.861,80.218 r180 bottom value=10.0k
R61 "RK73H1ETTP1002F" 0402 111.782,73.043 r180 bottom value=10.0k
R62 "RMCF0402JT10R0" 0402 119.45,16.458 r0 bottom value=10.0
R63 "CRCW04020000Z0ED" 0402 182.824,44.161 r180 top value=0
R64 "CRCW04020000Z0ED" 0402 182.824,45.206 r180 top value=0
R65 "RK73H1ETTP1002F" 0402 111.861,77.697 r180 bottom value=10.0k
R66 "RK73H1ETTP1002F" 0402 111.782,70.443 r180 bottom value=10.0k
R67 "CRCW04021K00FKED" 0402 120.91,84.878 r0 bottom value=1.00k
R68 "CRCW04020000Z0ED" 0402 121.88,69.455 r90 bottom value=0
R69 "CRCW040215K0FKED" 0402 114.521,67.783 r180 bottom value=15.0k
R70 "CRCW04020000Z0ED" 0402 205,96.425 r180 top value=0
R71 "CRCW04020000Z0ED" 0402 203.234,100.822 r180 top value=0
R72 "CRCW04020000Z0ED" 0402 169.656,59.468 r180 top value=0
R73 "RMCF0402JT10R0" 0402 121.205,60.672 r180 bottom value=10.0
R74 "RMCF0402JT10R0" 0402 121.208,63.211 r180 bottom value=10.0
R75 "CRCW040215K0FKED" 0402 115.139,66.178 r0 bottom value=15.0k
R76 "RMCF0402JT10R0" 0402 113.666,59.791 r180 bottom value=10.0
R77 "RMCF1206ZT0R00" FP-RMCF1206ZT0R00_1206-MFG 162.709,105.299 r0 bottom value=0
R78 "ERA-2AEB752X" 0402 117.739,66.178 r0 bottom value=7.50k
R79 "RK73H1ETTP1002F" 0402 28.43,20.594 r270 bottom value=10.0k
R80 "CRCW04020000Z0ED" 0402 198.938,94.338 r180 top value=0
R81 "CRCW040249R9FKED" 0402 209.121,4.7 r0 top value=49.9
R82 "CRCW04020000Z0ED" 0402 169.648,49.206 r180 top value=0
R83 "CRCW04020000Z0ED" 0402 182.69,54.006 r270 top value=0
R87 "CRCW04021K00FKED" 0402 186.513,101.726 r180 top value=1.00k
R91 "RK73H1ETTP3301F" 0402 186.467,105.615 r0 top value=3.30k
R92 "CRCW04023K65FKED" 0402 206.496,102.853 r90 top value=3.65k
R93 "CRCW040230K0FKED" 0402 205.861,100.822 r0 top value=30.0k
R94 "CRCW0402100KFKED" 0402 205.7,94.375 r90 top value=100k
R95 "RK73H1ETTP3301F" 0402 186.513,102.972 r0 top value=3.30k
R96 "CRCW04021K00FKED" 0402 186.467,106.696 r180 top value=1.00k
R97 "RK73H1ETTP1002F" 0402 161.975,116.85 r90 top value=10.0k
R98 "CRCW04020000Z0ED" 0402 209.115,1.629 r0 top value=0
R99 "RK73H1ETTP1002F" 0402 206.597,4.7 r0 top value=10.0k
R100 "RK73H1ETTP1002F" 0402 206.597,1.629 r0 top value=10.0k
R101 "ERJ-2RKF2001X" 0402 203.934,5.751 r0 top value=2.00k
R102 "ERJ-2RKF2001X" 0402 203.765,2.854 r0 top value=2.00k
R103 "RK73H1ETTP1002F" 0402 36.25,18.962 r270 bottom value=10.0k
R104 "ERJ-8ENF8453V" 1206 18.879,116.846 r270 top value=845k
R105 "ERJ-8ENF8453V" 1206 20.72,113.088 r0 top value=845k
R106 "ERJ-8ENF8453V" 1206 23.951,115.636 r0 top value=845k
R107 "CRCW04020000Z0ED" 0402 28.195,112.896 r180 top value=0
R108 "CRCW12069K09FKEA" 1206 25.618,111.631 r90 top value=9.09k
R109 "CRCW040215K0FKED" 0402 119.198,78.196 r270 bottom value=15.0k
R110 "CRCW0402100RFKED" 0402 33.733,14.393 r270 bottom value=100
R111 "CRCW04023K65FKED" 0402 31.3,17.225 r270 bottom value=3.65k
R112 "RMCF0402JT10R0" 0402 118.592,76.203 r0 bottom value=10.0
R113 "RMCF0402JT10R0" 0402 118.429,68.754 r0 bottom value=10.0
R114 "CRCW04021K00FKED" 0402 32.52,14.46 r90 bottom value=1.00k
R115 "CRCW0402100RFKED" 0402 37.547,19 r270 bottom value=100
R116 "CRCW040215K0FKED" 0402 114.56,76.211 r180 bottom value=15.0k
R117 "RMC1JPTE" 2512 50.525,80.215 r225 top value=0
R118 "RMC1JPTE" 2512 68.675,49.3 r45 bottom value=0
R119 "RMCF1206ZT0R00" FP-RMCF1206ZT0R00_1206-MFG 22.825,108.025 r0 top value=0
R120 "RMC1JPTE" 2512 38.396,89.467 r90 top value=0
R121 "RMC1JPTE" 2512 34.501,89.359 r90 bottom value=0
R122 "RMC1JPTE" 2512 52.718,76.818 r225 top value=0
R123 "RMC1JPTE" 2512 52.725,76.75 r225 bottom value=0
R124 "RMC1JPTE" 2512 50.612,80.182 r225 bottom value=0
R125 "CRCW0402100RFKED" 0402 111.536,52.89 r180 bottom value=100
R126 "RMC1JPTE" 2512 38.396,89.359 r90 bottom value=0
R127 "RMC1JPTE" 2512 2.686,70.291 r45 bottom value=0
R128 "RMC1JPTE" 2512 21.55,59.675 r225 bottom value=0
R129 "RMC1JPTE" 2512 12.205,67.275 r90 bottom value=0
R130 "RK73H1ETTP1002F" 0402 120.29,49.764 r180 bottom value=10.0k
R131 "CRCW0402100RFKED" 0402 121.56,54.043 r0 bottom value=100
R132 "RMC1JPTE" 2512 25.22,82.383 r0 bottom value=0
R133 "RMC1JPTE" 2512 25.2,78.192 r0 bottom value=0
R134 "RK73H1ETTP1002F" 0402 111.531,40.956 r0 bottom value=10.0k
R135 "RK73H1ETTP1002F" 0402 111.531,39.725 r0 bottom value=10.0k
R136 "RK73H1ETTP1002F" 0402 113.932,49.004 r90 bottom value=10.0k
R137 "RK73H1ETTP1002F" 0402 115.157,49.004 r90 bottom value=10.0k
T1 "FC-SCT2010-100T" CST2010 94.548,98.658 r90 bottom value=8.5mH
TP1 "0312-0-15-15-34-27-10-0" Mill-Max_0312-0-15-15-34-27-10-0 59.969,89.8 r0 top
TP2 "0312-0-15-15-34-27-10-0" Mill-Max_0312-0-15-15-34-27-10-0 59.969,93.6 r0 top
TP3 "TP_H0.45P0.75" TP_H045P075 209.36,101.753 r90 top
TP4 "TP_H0.45P0.75" TP_H045P075 209.36,103.696 r90 top
TP5 "0312-0-15-15-34-27-10-0" Mill-Max_0312-0-15-15-34-27-10-0 59.969,83.5 r0 top
TP6 "0312-0-15-15-34-27-10-0" Mill-Max_0312-0-15-15-34-27-10-0 59.969,79.7 r0 top
TP7 "0312-0-15-15-34-27-10-0" Mill-Max_0312-0-15-15-34-27-10-0 59.969,103.08 r0 top
TP8 "0312-0-15-15-34-27-10-0" Mill-Max_0312-0-15-15-34-27-10-0 59.969,99.28 r0 top
TP9 "0312-0-15-15-34-27-10-0" Mill-Max_0312-0-15-15-34-27-10-0 59.969,33.3 r0 top
TP10 "0312-0-15-15-34-27-10-0" Mill-Max_0312-0-15-15-34-27-10-0 59.969,37.1 r90 top
TP11 "0312-0-15-15-34-27-10-0" Mill-Max_0312-0-15-15-34-27-10-0 59.969,27 r0 top
TP12 "0312-0-15-15-34-27-10-0" Mill-Max_0312-0-15-15-34-27-10-0 59.969,23.2 r90 top
TP13 "0312-0-15-15-34-27-10-0" Mill-Max_0312-0-15-15-34-27-10-0 59.969,46.58 r90 top
TP14 "0312-0-15-15-34-27-10-0" Mill-Max_0312-0-15-15-34-27-10-0 59.969,42.78 r90 top
U1 "TMUX1309QDYYRQ1" DYY0016A 116.639,52.619 r180 bottom
U2 "TMUX1309QDYYRQ1" DYY0016A 116.587,43.519 r180 bottom
U3 "TCAN1043ADYYRQ1" DYY0014A-MFG 201.3,97.925 r90 top
U4 "SN74AHC1G08QDBVRQ1" DBV0005A_N 116.572,31.443 r0 bottom
U5 "TLV365QDBVRQ1" DBV0005A-MFG 115.259,86.288 r90 bottom
U6 "TMCS1133B2QDVGR" DVG0010A-MFG 34.368,26.8 r270 bottom
U7 "INA296A4QDDFRQ1" DDF0008A-MFG 115.969,15.307 r0 bottom
U9 "AMC3311QDWERQ1" DWE0016A-MFG 37.343,110.991 r0 bottom
U10 "INA225AQDGKRQ1" DGK0008A_N 116.798,61.994 r90 bottom
U11 "TLV9001QDBVRQ1" DBV0005A-MFG 115.255,78.997 r90 bottom
U12 "AMC1311BQDWVRQ1" DWV0008A-MFG 38.018,112.266 r0 top
U13 "TLV9001QDBVRQ1" DBV0005A-MFG 115.332,71.743 r90 bottom
U14 "SN74AHC08QPWRG4Q1" PW0014A_N 116.427,23.483 r0 bottom
VIN "5000" Keystone5000 0.225,28.775 r0 top
VIN "0312-0-15-15-34-27-10-0" Mill-Max_0312-0-15-15-34-27-10-0 12.729,123.225 r0 top
VMID "5000" Keystone5000 16.193,70.079 r90 top
VOUT "5000" Keystone5000 242.3,36.6 r90 top
ZZ1 "This Assembly Note is for PCB labels only" AssemblyNoteLabel 3.949,161.275 r0 top
ZZ2 "These assemblies are ESD sensitive, ESD precautions shall be observed." AssemblyNote 3.949,158.509 r0 top
ZZ3 "These assemblies must be clean and free from flux and all contaminants. Use of no clean flux is not acceptable." AssemblyNote 3.949,156.26 r0 top
ZZ4 "These assemblies must comply with workmanship standards IPC-A-610 Class 2, unless otherwise specified." AssemblyNote 3.949,154.011 r0 top

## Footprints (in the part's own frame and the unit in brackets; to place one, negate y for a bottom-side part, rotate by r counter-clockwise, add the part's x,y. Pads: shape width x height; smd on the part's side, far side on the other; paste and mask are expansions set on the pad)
0402 [mm] "0402 from SM-752 data"
  rect 0.8x0.6 smd: 1(-0.6,0) 2(0.6,0)
  silkscreen extent -1.22,-0.52 1.22,0.52, body extent -0.55,-0.3 0.55,0.3, height 0.6
0603 [mm] "0603 from SM-752 data"
  rect 1x0.95 smd: 1(-0.8,0) 2(0.8,0)
  silkscreen extent -1.52,-0.69 1.52,0.69, body extent -0.87,-0.47 0.87,0.47, height 1
0603S [mil]
  rect 20x35 smd: 1(-30,0) 2(30,0)
  body extent -34,-19 34,19, height 39
1206 [mm] "1206 from SM-752 data"
  rect 1.3x1.85 smd: 1(-1.45,0) 2(1.45,0)
  silkscreen extent -2.4,-1.21 2.4,1.21, body extent -1.7,-0.9 1.7,0.9, height 1.35
1206_180 [mm] "1206_180"
  rect 1.1x1.6 smd: 1(-1.7,0) 2(1.7,0)
  silkscreen extent -0.9,-1 0.9,1, body extent -1.75,-0.95 1.75,0.95, height 1.8
1206L#1 [mm] "1206 from SM-752 data"
  rect 1.1x1.75 smd: 1(-1.725,0) 2(1.675,0)
  silkscreen extent -0.4,-0.77 0.4,0.77, body extent -1.7,-0.9 1.7,0.9, height 1.35
1206L#2 [mm] "1206 from SM-752 data"
  rect 1.1x1.75 smd: 1(-1.725,0.039) 2(1.675,0.039)
  silkscreen extent -0.4,-0.77 0.4,0.77, body extent -1.7,-0.9 1.7,0.9, height 1.35
1210_150 [mm] "1210"
  rect 1.3x2.7 smd: 1(-1.45,0) 2(1.45,0)
  silkscreen extent -2.32,-1.57 2.32,1.57, body extent -1.7,-1.35 1.7,1.35, height 1.5
1210_280 [mm] "SMD, 2-Leads, Body 3.6x2.8mm, Height 2.8mm"
  rect 1.1x2.2 smd: 1(-1.65,0) 2(1.65,0)
  silkscreen extent -0.84,-1.4 0.84,1.4, body extent -1.8,-1.4 1.8,1.4, height 2.8
2220_280 [mm] "Chip Capacitor, Body 5.7x5.0mm, IPC Medium Density"
  rect 1.6x5.3 smd: 1(-2.6,0) 2(2.6,0)
  silkscreen extent -3.69,-2.94 3.69,2.94, body extent -2.95,-2.62 2.95,2.62, height 2.8
2512 [mm] "Chip Resistor, Body 6.3x3.2mm, IPC Medium Density"
  rect 1.3x3.4 smd: 1(-2.95,0) 2(2.95,0)
  silkscreen extent -1.9,-1.6 1.9,1.6, body extent -3.22,-1.67 3.22,1.67, height 0.71
ACT45B [mm] "SMD, 4-Leads, Body 4.7 x 3.7 mm"
  rect 1.35x0.9 smd: 1(-2.275,1.25) 2(-2.275,-1.25) 3(2.275,-1.25) 4(2.275,1.25)
  silkscreen extent -2.35,-1.7 2.35,2, body extent -2.35,-1.7 2.35,1.7, height 3
AssemblyNote [mm] "Assembly Note"
AssemblyNoteLabel [mm] "Assembly Note for PCB Labels"
B41896_1600x3150 [mm] "TH, 2-Leads, Dia 16mm, Lead Spacing 7.5mm"
  rect 1.6x1.6 hole 1.1: 1(-3.75,0)
  round 1.6 hole 1.1: 2(3.75,0)
  silkscreen extent -8.25,-8.25 8.25,8.25, body extent -8.25,-8.25 8.26,8.25, height 33.51
CE_Mark_5mm [mm] "Minimum text height for CE Mark"
  silkscreen extent -3.5,-2.5 3.5,2.5
controlCARD-120HSEC [mm] "Pads are not numbered according to Samtec datasheet."
  rect 0.5x2.724 smd: 1(-23.357,-1.678) 2(-23.357,1.722) 3(-22.557,-1.678) 4(-22.557,1.722) 5(-21.757,-1.678) 6(-21.757,1.722) 7(-20.957,-1.678) 8(-20.957,1.722) 9(-20.157,-1.678) 10(-20.157,1.722) 11(-19.357,-1.678) 12(-19.357,1.722) 13(-18.557,-1.678) 14(-18.557,1.722) 15(-17.757,-1.678) 16(-17.757,1.722) 17(-16.957,-1.678) 18(-16.957,1.722) 19(-16.157,-1.678) 20(-16.157,1.722) 21(-15.357,-1.678) 22(-15.357,1.722) 23(-14.557,-1.678) 24(-14.557,1.722) 25(-13.757,-1.678) 26(-13.757,1.722) 27(-12.957,-1.678) 28(-12.957,1.722) 29(-12.157,-1.678) 30(-12.157,1.722) 31(-11.357,-1.678) 32(-11.357,1.722) 33(-10.557,-1.678) 34(-10.557,1.722) 35(-9.757,-1.678) 36(-9.757,1.722) 37(-8.957,-1.678) 38(-8.957,1.722) 39(-8.157,-1.678) 40(-8.157,1.722) 41(-7.357,-1.678) 42(-7.357,1.722) 43(-6.557,-1.678) 44(-6.557,1.722) 45(-5.757,-1.678) 46(-5.757,1.722) 47(-4.957,-1.678) 48(-4.957,1.722) 49(-4.157,-1.678) 50(-4.157,1.722) 51(-3.357,-1.678) 52(-3.357,1.722) 53(-2.557,-1.678) 54(-2.557,1.722) 55(-1.757,-1.678) 56(-1.757,1.722) 57(2.243,-1.678) 58(2.243,1.722) 59(3.043,-1.678) 60(3.043,1.722) 61(3.843,-1.678) 62(3.843,1.722) 63(4.643,-1.678) 64(4.643,1.722) 65(5.443,-1.678) 66(5.443,1.722) 67(6.243,-1.678) 68(6.243,1.722) 69(7.043,-1.678) 70(7.043,1.722) 71(7.843,-1.678) 72(7.843,1.722) 73(8.643,-1.678) 74(8.643,1.722) 75(9.443,-1.678) 76(9.443,1.722) 77(10.243,-1.678) 78(10.243,1.722) 79(11.043,-1.678) 80(11.043,1.722) 81(11.843,-1.678) 82(11.843,1.722) 83(12.643,-1.678) 84(12.643,1.722) 85(13.443,-1.678) 86(13.443,1.722) 87(14.243,-1.678) 88(14.243,1.722) 89(15.043,-1.678) 90(15.043,1.722) 91(15.843,-1.678) 92(15.843,1.722) 93(16.643,-1.678) 94(16.643,1.722) 95(17.443,-1.678) 96(17.443,1.722) 97(18.243,-1.678) 98(18.243,1.722) 99(19.043,-1.678) 100(19.043,1.722) 101(19.843,-1.678) 102(19.843,1.722) 103(20.643,-1.678) 104(20.643,1.722) 105(21.443,-1.678) 106(21.443,1.722) 107(22.243,-1.678) 108(22.243,1.722) 109(23.043,-1.678) 110(23.043,1.722) 111(23.843,-1.678) 112(23.843,1.722) 113(24.643,-1.678) 114(24.643,1.722) 115(25.443,-1.678) 116(25.443,1.722) 117(26.243,-1.678) 118(26.243,1.722) 119(27.043,-1.678) 120(27.043,1.722)
  round 0.025 hole 1.27 unplated mask+0.876: 181(-24.857,0.022) 182(28.543,1.522)
  round 1.348 hole 0.84: 185(-27.207,0.022) 186(30.893,0.022)
  silkscreen extent -32.11,-3.86 35.8,3.9, body extent -31.75,-3.48 35.3,3.52, height 12.35
controlCARD-180HSEC-60pinAddon [mm] "Pads are not numbered according to datasheet."
  round 0.025 hole 1.27 unplated mask+0.876: 61(-13.1,0) 62(13.1,1.5)
  rect 0.5x2.724 smd: 121(-11.6,-1.7) 122(-11.6,1.7) 123(-10.8,-1.7) 124(-10.8,1.7) 125(-10,-1.7) 126(-10,1.7) 127(-9.2,-1.7) 128(-9.2,1.7) 129(-8.4,-1.7) 130(-8.4,1.7) 131(-7.6,-1.7) 132(-7.6,1.7) 133(-6.8,-1.7) 134(-6.8,1.7) 135(-6,-1.7) 136(-6,1.7) 137(-5.2,-1.7) 138(-5.2,1.7) 139(-4.4,-1.7) 140(-4.4,1.7) 141(-3.6,-1.7) 142(-3.6,1.7) 143(-2.8,-1.7) 144(-2.8,1.7) 145(-2,-1.7) 146(-2,1.7) 147(-1.2,-1.7) 148(-1.2,1.7) 149(-0.4,-1.7) 150(-0.4,1.7) 151(0.4,-1.7) 152(0.4,1.7) 153(1.2,-1.7) 154(1.2,1.7) 155(2,-1.7) 156(2,1.7) 157(2.8,-1.7) 158(2.8,1.7) 159(3.6,-1.7) 160(3.6,1.7) 161(4.4,-1.7) 162(4.4,1.7) 163(5.2,-1.7) 164(5.2,1.7) 165(6,-1.7) 166(6,1.7) 167(6.8,-1.7) 168(6.8,1.7) 169(7.6,-1.7) 170(7.6,1.7) 171(8.4,-1.7) 172(8.4,1.7) 173(9.2,-1.7) 174(9.2,1.7) 175(10,-1.7) 176(10,1.7) 177(10.8,-1.7) 178(10.8,1.7) 179(11.6,-1.7) 180(11.6,1.7)
  silkscreen extent -14.68,-3.88 14.68,3.88, body extent -14.3,-3.5 14.3,3.5, height 7.95
CST2010 [mm] "Coilcraft Current Sense Transformer"
  rrect8% 2.34x1.19 smd: 1(-9.04,5.08) 2(-9.04,2.54) 3(-9.04,0) 4(-9.04,-2.54) 5(-9.04,-5.08) 6(9.04,-5.08) 7(9.04,-2.54) 8(9.04,0) 9(9.04,2.54) 10(9.04,5.08)
  rrect2% 7.24x4.27 smd: 11(-0.1,5.62) 12(0,-5.62)
  body extent -9.6,-7.27 9.6,7.27, height 10.82
DBV0005A-MFG [mm]
  rrect17% 1.1x0.6 smd paste+0 mask+0: 1(-1.3,0.95) 2(-1.3,0) 3(-1.3,-0.95) 4(1.3,-0.95) 5(1.3,0.95)
  silkscreen extent -2.57,-1.53 0.87,1.53, body extent -1.4,-1.45 1.4,1.45, height 1.45
DBV0005A_N [mm] "SOT23, 5-Leads, Body 2.9x1.6mm, Pitch 0.95mm, Lead Span 2.8mm, IPC Medium Density"
  rrect17% 1x0.6 smd: 1(-1.375,0.95) 2(-1.375,0) 3(-1.375,-0.95) 4(1.375,-0.95) 5(1.375,0.95)
  silkscreen extent -1.63,-1.55 0.38,1.55, body extent -1.42,-1.46 1.42,1.46, height 1.09
DDF0008A-MFG [mm]
  rrect22% 1.05x0.45 smd paste+0 mask+0: 1(-1.3,0.975) 2(-1.3,0.325) 3(-1.3,-0.325) 4(-1.3,-0.975) 5(1.3,-0.975) 6(1.3,-0.325) 7(1.3,0.325) 8(1.3,0.975)
  silkscreen extent -2.5,-1.48 0.4,1.48, body extent -1.41,-1.45 1.41,1.45, height 1.1
DGK0008A_N [mm] "TSOP, 8-Leads, Body 3x3mm, Pitch 0.65mm, IPC Medium Density"
  oval 1.35x0.45 smd: 1(-2.225,0.975) 2(-2.225,0.325) 3(-2.225,-0.325) 4(-2.225,-0.975) 5(2.225,-0.975) 6(2.225,-0.325) 7(2.225,0.325) 8(2.225,0.975)
  silkscreen extent -2.75,-1.55 0.95,1.55, body extent -2.45,-1.5 2.45,1.5, height 0.96
DVG0010A-MFG [mm]
  rrect6% 1.65x4.41 smd paste+0 mask+0: 1(-4.875,2.54) 2(-4.875,-2.54)
  rrect17% 1.65x0.6 smd paste+0 mask+0: 3(4.875,-4.445) 4(4.875,-3.175) 5(4.875,-1.905) 6(4.875,-0.635) 7(4.875,0.635) 8(4.875,1.905) 9(4.875,3.175) 10(4.875,4.445)
  silkscreen extent -6.37,-5.25 3.67,5.25, body extent -5.15,-5.15 5.15,5.15, height 2.65
DWE0016A-MFG [mm]
  rrect17% 1.65x0.6 smd paste+0 mask+0: 1(-4.875,4.445) 2(-4.875,3.175) 3(-4.875,1.905) 4(-4.875,0.635) 5(-4.875,-0.635) 6(-4.875,-1.905) 7(-4.875,-3.175) 8(-4.875,-4.445) 9(4.875,-4.445) 10(4.875,-3.175) 11(4.875,-1.905) 12(4.875,-0.635) 13(4.875,0.635) 14(4.875,1.905) 15(4.875,3.175) 16(4.875,4.445)
  silkscreen extent -6.37,-5.25 3.5,5.25, body extent -5.17,-5.15 5.17,5.15, height 2.65
DWV0008A-MFG [mm]
  rrect17% 1.8x0.6 smd paste+0 mask+0: 1(-5.45,1.905) 2(-5.45,0.635) 3(-5.45,-0.635) 4(-5.45,-1.905) 5(5.45,-1.905) 6(5.45,-0.635) 7(5.45,0.635) 8(5.45,1.905)
  silkscreen extent -7.1,-2.98 3.8,2.98, body extent -5.75,-2.93 5.75,2.93, height 2.8
DYY0014A-MFG [mm]
  rrect33% 1.05x0.3 smd paste+0 mask+0: 1(-1.5,1.5) 2(-1.5,1) 3(-1.5,0.5) 4(-1.5,0) 5(-1.5,-0.5) 6(-1.5,-1) 7(-1.5,-1.5) 8(1.5,-1.5) 9(1.5,-1) 10(1.5,-0.5) 11(1.5,0) 12(1.5,0.5) 13(1.5,1) 14(1.5,1.5)
  silkscreen extent -2.72,-2.15 1.05,2.15, body extent -2.12,-2.4 2.12,2.4, height 0.25
DYY0016A [mm] "SOP, 16-Leads, Body 2x4.2mm, Pitch 0.5mm"
  rrect33% 1.05x0.3 smd: 1(-1.5,1.75) 2(-1.5,1.25) 3(-1.5,0.75) 4(-1.5,0.25) 5(-1.5,-0.25) 6(-1.5,-0.75) 7(-1.5,-1.25) 8(-1.5,-1.75) 9(1.5,-1.75) 10(1.5,-1.25) 11(1.5,-0.75) 12(1.5,-0.25) 13(1.5,0.25) 14(1.5,0.75) 15(1.5,1.25) 16(1.5,1.75)
  body extent -1.63,-2.1 1.63,2.1, height 1.02
FCC_disclaimer [mm]
FP-B58035U7105M052_SMD2-MFG [mm] "Recommended Land Pattern"
  rrect4% 2.85x7 smd paste+0 mask+0: 1(-3.925,0) 2(3.925,0)
  silkscreen extent -2.12,-3.25 2.12,3.25, body extent -3.7,-3 3.7,3, height 9.15
FP-FLE-105-01-G-DV_HDR10-MFG [mm]
  rrect14% 0.74x1.675 smd paste+0 mask+0: 1(-2.54,1.843) 2(-2.54,-1.843) 3(-1.27,1.843) 4(-1.27,-1.843) 5(0,1.843) 6(0,-1.843) 7(1.27,1.843) 8(1.27,-1.843) 9(2.54,1.843) 10(2.54,-1.843)
  silkscreen extent -3.3,-1.73 3.3,3.45, body extent -3.23,-2.3 3.23,2.3, height 4.67
FP-MBR130T3G_SOD123-MFG [mil]
  rrect11% 36x48 smd paste+0 mask+0: 1(-64.5,0) 2(64.5,0)
  silkscreen extent -110,-35 32,35, body extent -72,-31 72,31, height 53
FP-RMCF1206ZT0R00_1206-MFG [mm]
  rrect10% 1x1.6 smd paste+0 mask+0: 1(-1.6,0) 2(1.6,0)
  silkscreen extent -0.72,-0.87 0.72,0.87, body extent -1.6,-0.8 1.6,0.8, height 0.7
IEC_HighVoltage_Small [mm]
  silkscreen extent -2.72,-2.24 2.72,2.47
IEC_HotSurface_Small [mm]
  silkscreen extent -2.72,-2.36 2.72,2.35
Keystone5000 [mil] "For Keystone 500x miniature loop terminals"
  round 80 hole 40: 1(0,0)
  silkscreen extent -52,-52 52,52, body extent -49,-49 49,49, height 182
Keystone5001 [mil] "For Keystone 500x miniature loop terminals"
  round 80 hole 40: 1(0,0)
  silkscreen extent -52,-52 52,52, body extent -49,-49 49,49, height 182
Label_650x200 [mil] "Thermal Transfer Label"
  round 1 on Mech13: 0(0,0)
  silkscreen extent -325,-100 325,100, body extent -325,-100 325,100, height 1
LED_LTST-C190 [mm] "Lite-On"
  rect 0.8x0.8 smd: 1(-0.75,0) 2(0.75,0)
  silkscreen extent -1.1,-0.8 1.8,0.8, body extent -0.85,-0.45 0.85,0.45, height 0.9
LED_LTST-C190_Red [mm] "Lite-On"
  rect 0.8x0.8 smd: 1(-0.75,0) 2(0.75,0)
  silkscreen extent -1.1,-0.8 1.8,0.8, body extent -0.85,-0.45 0.85,0.45, height 0.9
Mill-Max_0312-0-15-15-34-27-10-0 [mm] "Pin Receptacle, .032-.046\" .075\" Dia, Gold, TH"
  round 2.45 hole 1.905: 1(0,0)
  silkscreen extent -1.52,-1.52 1.52,1.52, body extent -1.15,-1.15 1.16,1.15, height 0.46
Nichicon_3000x4500_Snap [mm] "TH, 2-Leads, Dia 30mm, Pin Spacing 10mm"
  rrect50% 3x3 hole 2: 1(-5,0)
  round 3 hole 2: 2(5,0)
  silkscreen extent -15.75,-15.75 15.75,15.75, body extent -15.75,-15.75 15.76,15.75, height 47.01
NORCOMP_182-009-213R171 [mm] "Connector; D Subminiature 9 Position; Right Angle"
  rect 1.8x1.8 hole 1.092: 1(-5.54,-10.92)
  round 1.8 hole 1.092: 2(-2.77,-10.92) 3(0,-10.92) 4(2.77,-10.92) 5(5.54,-10.92) 6(-4.155,-8.08) 7(-1.385,-8.08) 8(1.385,-8.08) 9(4.155,-8.08)
  round 4.76 hole 3.05: 10(-12.495,-9.5) 11(12.495,-9.5)
  silkscreen extent -15.4,-12.4 15.4,6, body extent -15.41,-12.98 15.41,6.1, height 12.55
PW0014A_N [mm] "TSOP, 14-Leads, Body 5x4.4mm, Pitch 0.65mm, IPC Medium Density"
  oval 1.4x0.45 smd: 1(-2.95,1.95) 2(-2.95,1.3) 3(-2.95,0.65) 4(-2.95,0) 5(-2.95,-0.65) 6(-2.95,-1.3) 7(-2.95,-1.95) 8(2.95,-1.95) 9(2.95,-1.3) 10(2.95,-0.65) 11(2.95,0) 12(2.95,0.65) 13(2.95,1.3) 14(2.95,1.95)
  silkscreen extent -3.4,-2.55 1.85,2.55, body extent -3.21,-2.5 3.21,2.5, height 1
Samtec_CLP-103-02-x-D [mm] "Receptacle, 1.27mm, 3x2, SMT"
  rrect50% 1.47x0.74 smd: 1(1.615,1.27) 2(-1.615,1.27) 3(1.615,0) 4(-1.615,0) 5(1.615,-1.27) 6(-1.615,-1.27)
  silkscreen extent -1.52,-2.12 1.52,2.37, body extent -2.16,-2.12 2.16,2.12, height 2.29
Samtec_FLE-106-01-x-DV-A [mm] "Receptacle, 1.27mm, 6x2, SMT"
  rect 0.74x1.675 smd: 1(-3.175,1.843) 2(-3.175,-1.843) 3(-1.905,1.843) 4(-1.905,-1.843) 5(-0.635,1.843) 6(-0.635,-1.843) 7(0.635,1.843) 8(0.635,-1.843) 9(1.905,1.843) 10(1.905,-1.843) 11(3.175,1.843) 12(3.175,-1.843)
  silkscreen extent -4.1,-1.66 3.87,1.66, body extent -3.87,-2.3 3.87,2.3, height 4.55
Samtec_FLE-107-01-x-DV#1 [mm] "Receptacle, 1.27mm, 7x2, SMT"
  rect 0.74x1.675 smd: 1(-3.81,1.843) 2(-3.81,-1.843) 3(-2.54,1.843) 4(-2.54,-1.843) 5(-1.27,1.843) 6(-1.27,-1.843) 9(1.27,1.843) 10(1.27,-1.843) 11(2.54,1.843) 12(2.54,-1.843) 13(3.81,1.843) 14(3.81,-1.843)
  silkscreen extent -4.8,-1.66 4.5,1.66, body extent -4.5,-2.3 4.5,2.3, height 4.55
Samtec_FLE-107-01-x-DV#2 [mm] "Receptacle, 1.27mm, 7x2, SMT"
  rect 0.74x1.675 smd: 1(-3.81,1.843) 2(-3.81,-1.843) 3(-2.54,1.843) 4(-2.54,-1.843) 5(-1.27,1.843) 6(-1.27,-1.843) 7(0,1.843) 8(0,-1.843) 9(1.27,1.843) 10(1.27,-1.843) 11(2.54,1.843) 12(2.54,-1.843) 13(3.81,1.843) 14(3.81,-1.843)
  silkscreen extent -4.8,-1.66 4.5,1.66, body extent -4.5,-2.3 4.5,2.3, height 4.55
SCREW_TERMINAL_8199 [mil] "Keystone Teminal, 30 Amp"
  round 110 hole 76: 1(-197,98.63) 3(98.57,98.63) 4(98.57,-98.63) 6(-197,-98.63)
  silkscreen extent -265,-160 265,160, body extent -253,-177 254,177, height 325
SMAF [mm] "SMD, 2-Leads, Body 3.8x2.5mm"
  rect 1.24x1.89 smd: 1(-2.04,0) 2(2.04,0)
  silkscreen extent -3.4,-1.3 2.8,1.3, body extent -2.35,-1.25 2.35,1.25, height 1
SOD-523 [mm] "NXP Semiconductor recommended land pattern, nominal STEP model"
  rect 0.8x0.6 smd paste-0.05: 1(-0.55,0) 2(0.55,0)
  silkscreen extent -1.65,-0.66 1.2,0.66, body extent -0.8,-0.4 0.8,0.4, height 0.72
SOT-23 [mm] "SOT23, 3-Leads, Body 2.9x1.3mm, Pitch 0.95mm, Lead Span 2.5mm, IPC Medium Density"
  rrect50% 1x0.6 smd: 1(-1.2,0.95) 2(-1.2,-0.95) 3(1.2,0)
  silkscreen extent -1.63,-1.5 0.7,1.5, body extent -1.16,-1.45 1.21,1.45, height 1
Sullins_PRxC005SBAN-M71RC [mm] "Header, 2.54mm, 5x1, R/A, TH"
  rrect50% 1.5x1.5 hole 1: 1(-5.08,0)
  round 1.5 hole 1: 2(-2.54,0) 3(0,0) 4(2.54,0) 5(5.08,0)
  silkscreen extent -6.7,-4.02 6.35,-1.52, body extent -6.35,-9.86 6.35,0.32, height 2.5
TP_H045P075 [mm] "TP_H0.45P0.75"
  round 0.75 hole 0.45: 1(0,0)
WEEE_Minimum [mm] "WEEElie bin"
  silkscreen extent -2.42,-4.38 2.52,2.65

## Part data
12V BIAS_VIN VIN VMID VOUT: library part CMP-0055137-2, "Test Point, Miniature, Red, TH", Color=Red, Manufacturer="Keystone Electronics", Supplier Part Number 1=36-5000-ND
AGND BIAS_HS_12V PGND TP1 TP2 TP5 TP6 TP7 TP8 TP9 TP10 TP11 TP12 TP13 TP14 VIN: library part CMP-0055026-1, "Pin Receptacle, .032-.046\" .075\" Dia, Gold, TH", Manufacturer=Mill-Max, Supplier Part Number 1=0312-015153427100-ND
AGND BIAS_DGND DGND PGND: library part CMP-0055138-2, "Test Point, Miniature, Black, TH", Color=Black, Manufacturer="Keystone Electronics", Supplier Part Number 1=36-5001-ND
C1 C5: library part CMP-0010058-3, "CAP, AL, 120 uF, 600 V, +/- 20%, TH", Cap_Case=30x45mm, Manufacturer=Nichicon, Supplier Part Number 1=493-14690-ND, Tolerance_%=20%, Value1=Unknown, Value2=600V, ValueDisplayed=120uF
C2 C11 C12 C14 C16 C17: library part CMP-0010311-2, "CAP, AL, 1800 uF, 35 V, +/- 20%, 0.023 ohm, AEC-Q200 Grade 1, TH", Cap_Case=16x31.5mm, Manufacturer=TDK, Supplier Part Number 1=B41896C7188M-ND, Tolerance_%=20%, Value1="0.023 ohm", Value2=35V, ValueDisplayed=1800uF
C3 C4: library part CMP-0860865-1, "CAP, CERM, 0.47 µF, 630 V,+/- 20%, X7T, AEC-Q200 Grade 1, 2220", Cap_Case=2220, Manufacturer=TDK, TempCo=X7T, Tolerance_%=20%, Value2=630V, ValueDisplayed=0.47µF
C6 C56: library part CMP-0860380-1, "CAP, CERM, 0.01 µF, 630 V,+/- 5%, C0G/NP0, AEC-Q200 Grade 1, 1210", Cap_Case=1210, Manufacturer=TDK, TempCo=C0G/NP0, Tolerance_%=5%, Value2=630V, ValueDisplayed=0.01µF
C7 C8 C9 C10 C13 C18: library part CMP-0008788-2, "CAP, CERM, 2.2 uF, 50 V, +/- 10%, X7R, AEC-Q200 Grade 1, 1206", Cap_Case=1206_180, Manufacturer=TDK, Supplier Part Number 1=445-6986-1-ND, TempCo=X7R, Tolerance_%=10%, Value1="0.005887 ohm", Value2=50V, ValueDisplayed=2.2uF
C15 C25 C26 C27 C28 C31 C32 C33 C34 C36 C37 C38 C57 C58 C59 C60 C61 C62 C63 C64: library part CMP-0085350-1, "CAP, CERM, 10 µF, 50 V,+/- 10%, X7S, AEC-Q200 Grade 1, 1210", Cap_Case=1210, Manufacturer=TDK, TempCo=X7S, Tolerance_%=10%, Value2=50V, ValueDisplayed=10µF
C19 C20 C22 C29 C42 C44 C53 C76 C78 C79 C84 C88 C89 C95 C96 C99 C105 C106: library part CMP-0080610-1, "CAP, CERM, 0.1 µF, 25 V,+/- 10%, X7R, AEC-Q200 Grade 1, 0402", Cap_Case=0402, Manufacturer=TDK, Supplier Part Number 1=445-6902-1-ND, TempCo=X7R, Tolerance_%=10%, Value2=25V, ValueDisplayed=0.1µF
C21: library part CMP-0007088-4, "CAP, CERM, 4700 pF, 100 V, +/- 10%, X7R, AEC-Q200 Grade 1, 0603", Cap_Case=0603, Manufacturer=TDK, Supplier Part Number 1=445-5810-1-ND, TempCo=X7R, Tolerance_%=10%, Value1="0.469862 ohm", Value2=100V, ValueDisplayed=4700pF
C23: library part CMP-0008580-2, "CAP, CERM, 0.01 uF, 200 V, +/- 5%, C0G/NP0, AEC-Q200 Grade 1, 1206", Cap_Case=1206, Manufacturer=Kemet, Supplier Part Number 1=399-11573-1-ND, TempCo=C0G/NP0, Tolerance_%=5%, Value1=Unknown, Value2=200V, ValueDisplayed=0.01uF
C24 C35: library part CMP-0064911-2, "CAP, CERM, 10 pF, 50 V,+/- 2.5%, C0G/NP0, AEC-Q200 Grade 1, 0402", Cap_Case=0402, Manufacturer=AVX, Supplier Part Number 1=478-5991-1-ND, TempCo=C0G/NP0, Tolerance_%=2.5%, Value1=Unknown, Value2=50V, ValueDisplayed=10pF
C30 C45 C54 C55 C77 C87 C90 C91 C92 C93 C94 C98 C101 C102 C103: library part CMP-0085176-1, "CAP, CERM, 220 pF, 16 V,+/- 10%, X7R, AEC-Q200 Grade 1, 0402", Cap_Case=0402, Manufacturer=Yageo, TempCo=X7R, Tolerance_%=10%, Value2=16V, ValueDisplayed=220pF
C39 C40 C43 C48 C49 C50 C52 C65 C66 C67 C68: library part CMP-0079095-1, "CAP, CERM, 0.1 µF, 50 V,+/- 10%, X7R, AEC-Q200 Grade 1, 0603", Cap_Case=0603, Manufacturer=AVX, Supplier Part Number 1=478-3540-1-ND, TempCo=X7R, Tolerance_%=10%, Value2=50V, ValueDisplayed=0.1µF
